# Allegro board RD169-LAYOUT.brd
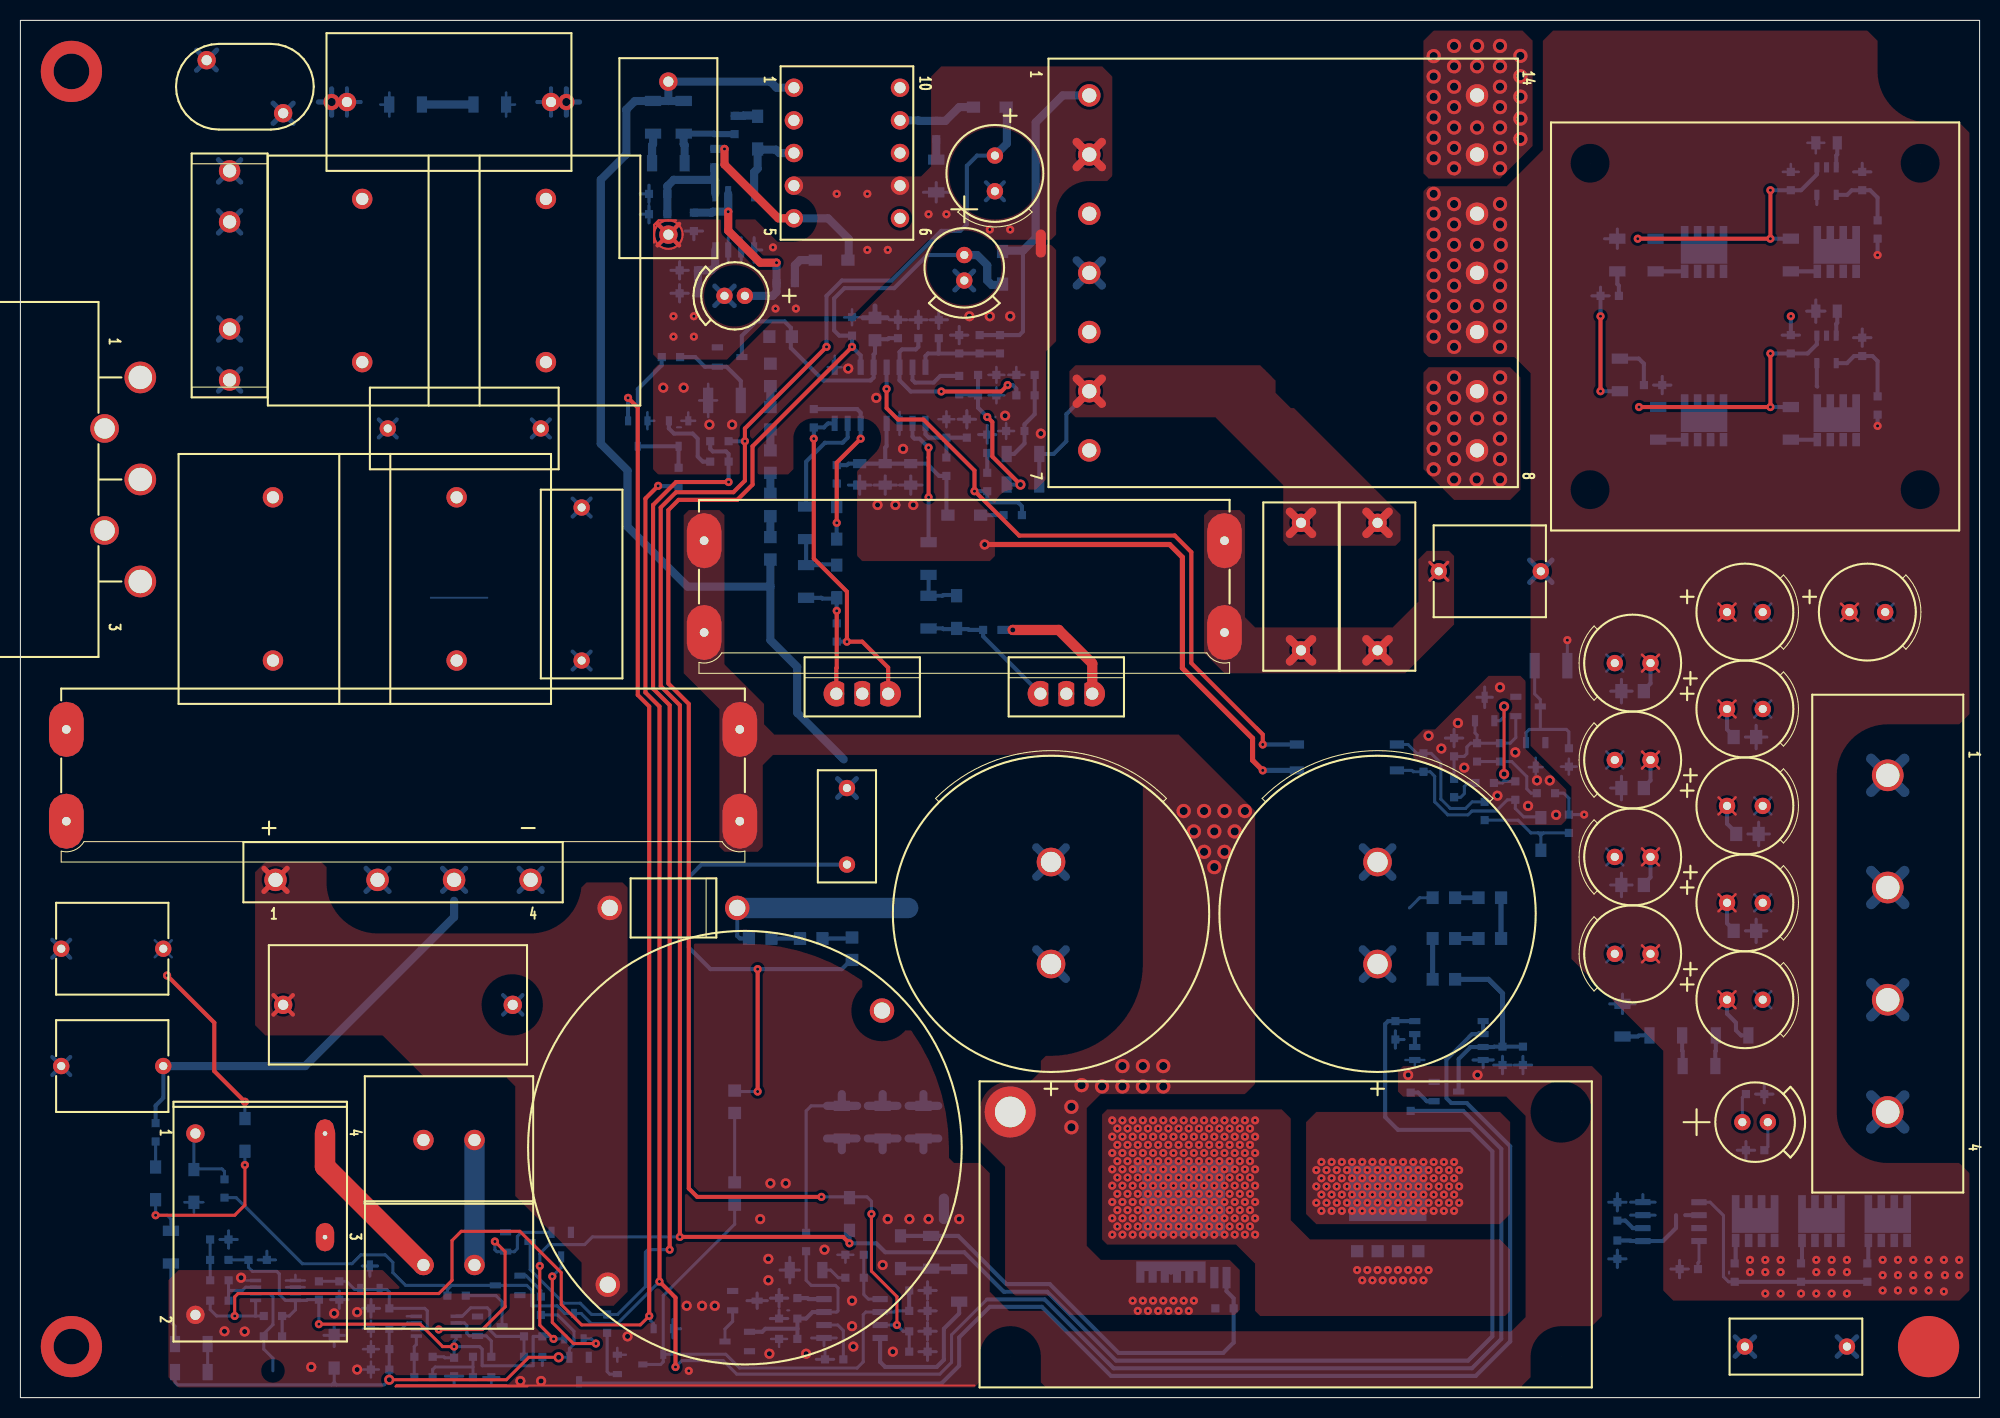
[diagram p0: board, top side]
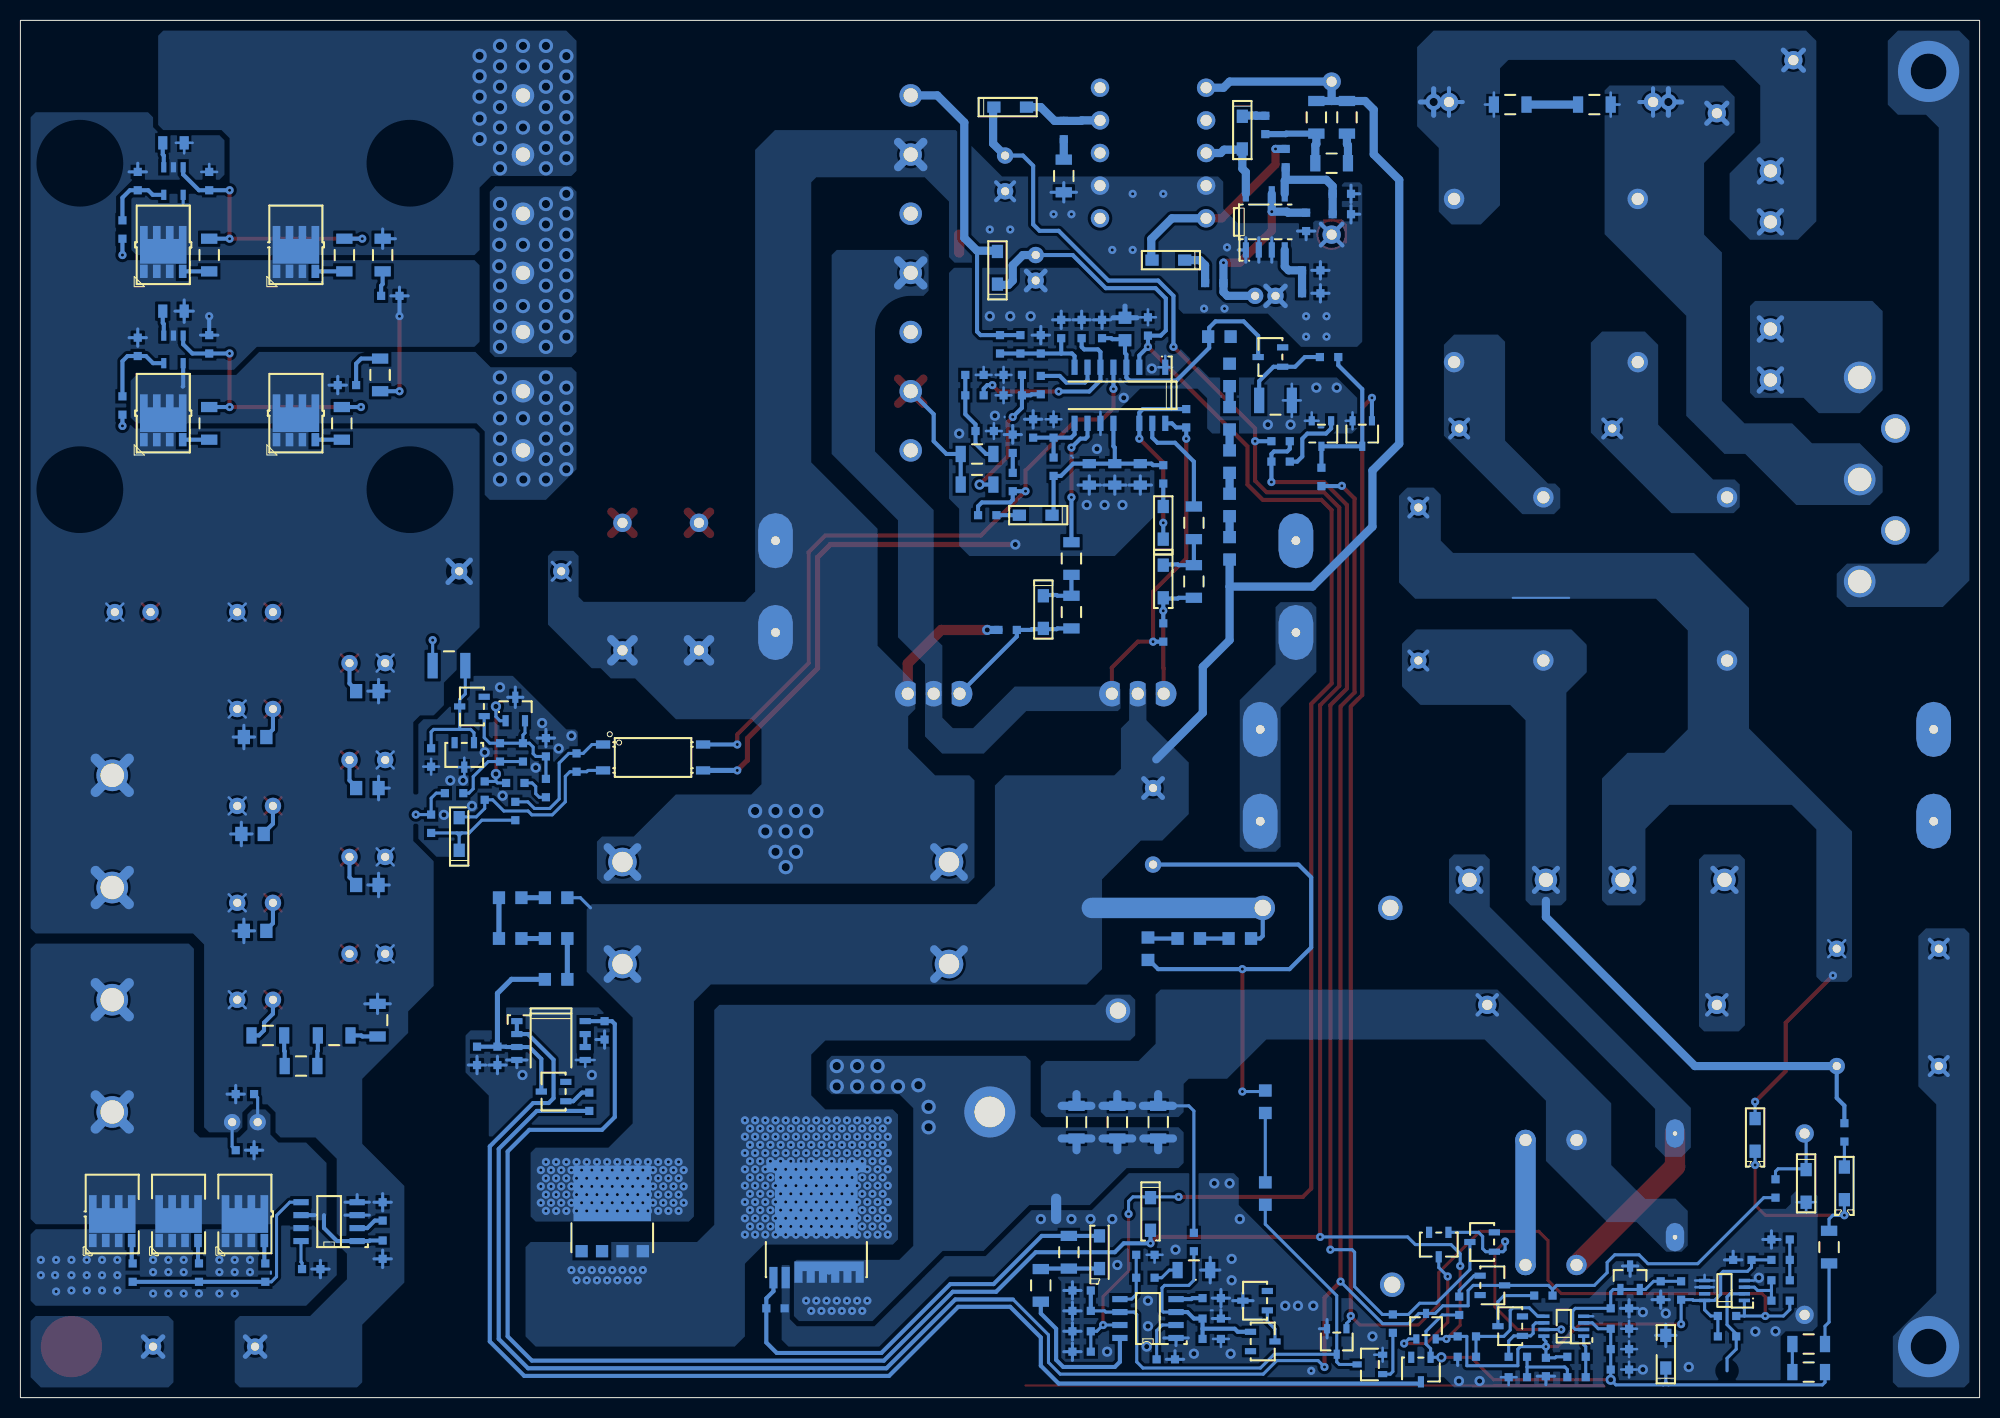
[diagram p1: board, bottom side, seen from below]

Outline 192 x 135 mm; copper layers: TOP, BOTTOM. Coordinates in mm from the lower left corner of the outline.
Outline path: rectangle 0,0 192,135

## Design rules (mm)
constraint set DEFAULT: 

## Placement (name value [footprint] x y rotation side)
C1  -  [RD10010SP01]  63.5 129 270 top
C2  -  [KC00080SP01]  35.25 4.75 180 bottom
C3  -  [KC00080SP01]  35.25 8.75 180 bottom
C4  -  [KC00140SP01]  65 125.5 270 bottom
C5  -  [RD10180SP01]  52 127 180 top
C6  -  [KC00080SP01]  75.25 7.75 180 bottom
C7  -  [KC00080SP01]  79.75 3.75 180 bottom
C8  -  [KC00080SP01]  45.25 2 0 bottom
C9  -  [RD10370SP01]  51 95 180 top
C10  -  [KC00080SP01]  66 115.25 270 bottom
C11  -  [DC03410SP01]  69 108 0 top
C12  -  [RD10370SP01]  55 72.25 90 top
C13  -  [RD10380SP01]  14 44 180 top
C14  -  [KC00140SP01]  77 12.5 180 bottom
C15  -  [RD10380SP01]  14 32.5 180 top
C16  -  [KC00080SP01]  81.75 14 180 bottom
C17  -  [KC00080SP01]  42.5 3 270 bottom
C18  -  [KC00080SP01]  89.75 124.25 270 bottom
C19  -  [KC00080SP01]  88 4.5 0 bottom
C20  -  [KC00080SP01]  88 6.5 0 bottom
C21  -  [KC00080SP01]  88 10.5 0 bottom
C22  -  [RD10300SP01]  95.5 118.25 90 top
C23  -  [RD10460SP02]  25.75 38.5 0 top
C24  -  [RD10450SP01]  81 59.75 270 top
C25  -  [KC00080SP01]  81.5 105 90 bottom
C26  -  [KC00080SP01]  86 104.75 90 bottom
C27  -  [KC00080SP01]  88 104.75 90 bottom
C28  -  [KC00080SP01]  90 104.75 90 bottom
C29  -  [DC903A0SP01]  69 97.75 180 bottom
C30  -  [KC00080SP01]  94.75 93.5 90 bottom
C31  -  [RD10210SP01]  133 52.5 270 top
C32  -  [RD10210SP01]  101 52.5 270 top
C33  -  [KC00080SP01]  23.25 13.5 0 bottom
C34  -  [KC00080SP01]  90.75 95 90 bottom
C35  -  [KC00080SP01]  147.25 33.5 270 bottom
C36  -  [KC00060SP02]  87.25 90.5 270 bottom
C37  -  [KC00060SP02]  84.75 90.5 270 bottom
C38  -  [KC00080SP01]  77.75 96 90 bottom
C39  -  [KC00060SP02]  82.25 90.5 270 bottom
C40  -  [KC00080SP01]  134.75 36 270 bottom
C41  -  [DC05080SP01]  92.5 109.5 90 top
C42  -  [RD10410SP01]  125.5 85.75 270 top
C43  -  [KC00080SP01]  31.25 10.5 270 bottom
C44  -  [KC00140SP01]  98.25 89.5 180 bottom
C45  -  [RD10410SP01]  133 85.75 270 top
C46  -  [KC00140SP01]  98.25 92.5 180 bottom
C47  -  [RD10380SP01]  139 81 0 top
C49  -  [KC00080SP01]  160 99.25 0 bottom
C50  -  [KC00080SP01]  155.75 108 0 bottom
C51  -  [KC00080SP01]  94.75 98.25 0 bottom
C52  -  [KC00080SP01]  94.75 100.25 0 bottom
C53  -  [KC00060SP02]  177 106.5 180 bottom
C54  -  [KC00080SP01]  180.5 103 90 bottom
C55  -  [KC00060SP02]  177 123 180 bottom
C56  -  [RD10300SP01]  182.75 77 180 top
C57  -  [RD10300SP01]  170.75 77 180 top
C58  -  [KC00080SP01]  180.5 119.25 90 bottom
C59  -  [RD10300SP01]  170.75 67.5 180 top
C60  -  [RD10300SP01]  170.75 58 180 top
C61  -  [RD10300SP01]  170.75 48.5 180 top
C62  -  [RD10300SP01]  170.75 39 180 top
C63  -  [RD10300SP01]  156.25 72 0 top
C64  -  [KC00080SP01]  143.5 60.25 0 bottom
C65  -  [KC00080SP01]  156.5 14.5 270 bottom
C66  -  [RD10300SP01]  156.25 62.5 0 top
C67  -  [RD10300SP01]  156.25 53 0 top
C68  -  [KC00080SP01]  142.75 63.25 90 bottom
C69  -  [RD10300SP01]  156.25 43.5 0 top
C70  -  [DC903A0SP01]  150 71.75 180 bottom
C71  -  [KC00060SP01]  169 64.75 0 bottom
C72  -  [KC00060SP01]  169.25 55.25 0 bottom
C73  -  [KC00080SP01]  163.5 12.6 0 bottom
C74  -  [KC00060SP01]  169 45.75 0 bottom
C75  -  [KC00060SP01]  158 69.25 180 bottom
C76  -  [KC00060SP01]  158 59.75 180 bottom
C77  -  [KC00060SP01]  158 50.25 180 bottom
C78  -  [DC05080SP01]  171.25 27 180 top
C79  -  [RD10430SP01]  179 5 180 top
C80  -  [KC00080SP01]  170 24.25 0 bottom
C81  -  [KC00080SP01]  170 29.75 0 bottom
D1  -  [MMK01670SP01]  13.25 21 270 bottom
D2  -  [MMK01670SP01]  22 25.75 270 bottom
D3  -  [MM10240SP01]  71 9.5 90 bottom
D4  -  [MM10240SP01]  47.75 11 270 bottom
D5  -  [MM10240SP01]  70.25 5.5 270 bottom
D6  -  [MMK01670SP01]  72.25 124 90 bottom
D7  -  [MM10240SP01]  46 7 90 bottom
D8  -  [MMK01670SP01]  79.5 111.5 180 bottom
D9  -  [MMK01670SP01]  81.25 18 90 bottom
D10  -  [D0001A0SP01]  25 50.75 0 top
D11  -  [MM10240SP01]  53 15 0 bottom
D12  -  [MM10240SP01]  48.75 15.25 90 bottom
D13  -  [MMK01670SP01]  17 20.75 90 bottom
D14  -  [MMK01670SP01]  95 126.5 0 bottom
D15  -  [RD10400SP01]  57.75 48 0 top
D16  -  [MMK01670SP01]  86.25 14.25 270 bottom
D17  -  [MM10240SP01]  139.75 30 90 bottom
D18  -  [MM11090SP01]  134 18.25 180 bottom
D19  -  [MM10240SP01]  69.5 102 90 bottom
D20  -  [MMK01670SP01]  80 80 90 bottom
D21  -  [MMK01670SP01]  91.75 77 90 bottom
D22  -  [MMK01670SP01]  80 85.75 270 bottom
D23  -  [MMK01670SP01]  96.25 110.75 270 bottom
D24  -  [MM10240SP01]  54.75 2.75 0 bottom
D25  -  [MM10240SP01]  147.75 67.75 90 bottom
D26  -  [MM10240SP01]  148.5 63 0 bottom
F1  -  [OD11240SP01]  20.5 99.75 90 top
HS1  -  [SE10220SP01]  70.5 65.5 180 top
HS2  -  [SE10240SP01]  97 28 0 top
HS3  -  [SE10160SP01]  153.82 89 0 top
HS4  -  [SE10230SP01]  118 84 180 top
L1  -  [OD11280SP01]  33.5 117.5 270 top
L2  -  [OD11280SP01]  24.75 88.25 270 top
L3  -  [OD11260SP01]  57.56 11.06 45 top
PC1  -  [MM11100SP01]  130 62.75 270 bottom
Q1  -  [DQ900A0SP01]  54.25 7 180 bottom
Q2  -  [DQ900A0SP01]  64.5 94.5 0 bottom
Q3  -  [DQ900A0SP01]  59.75 3.25 90 bottom
Q4  -  [DQ900A0SP01]  63 5.5 0 bottom
Q5  -  [DQ900A0SP01]  60.5 94.5 0 bottom
Q6  -  [MM11080SP01]  114 17 180 bottom
Q7  -  [SI10100SP01]  79.96 69 0 top
Q8  -  [SI10100SP01]  99.96 69 0 top
Q10  -  [SN00130SP01]  165 113 180 bottom
Q11  -  [SN00130SP01]  165 96.5 180 bottom
Q12  -  [SN00130SP01]  178 113 180 bottom
Q13  -  [SN00130SP01]  178 96.5 180 bottom
Q14  -  [SN00130SP01]  183 18 180 bottom
Q15  -  [SN00130SP01]  176.5 18 180 bottom
Q16  -  [SN00130SP01]  170 18 180 bottom
R1  -  [KC00080SP01]  35.25 6.75 180 bottom
R2  -  [KC00140SP01]  14.75 14.75 270 bottom
R3  -  [KC00140SP01]  16.75 5.25 0 bottom
R4  -  [KC00140SP01]  16.75 2.5 180 bottom
R5  -  [KC00080SP01]  35.25 2.75 180 bottom
R6  -  [KC00140SP01]  46 126.75 180 bottom
R7  -  [KC00140SP01]  37.75 126.75 180 bottom
R8  -  [KC00080SP01]  65.5 110.5 180 bottom
R9  -  [KC00080SP01]  51 9 90 bottom
R10  -  [KC00140SP01]  62 125.5 270 bottom
R11  -  [KC00140SP01]  63.5 121 0 bottom
R12  -  [KC00080SP01]  13.25 26 270 bottom
R13  -  [KC00080SP01]  65.5 108.25 180 bottom
R14  -  [KC00080SP01]  70 124.75 90 bottom
R15  -  [KC00080SP01]  75.25 5.75 180 bottom
R16  -  [KC00080SP01]  39.5 4 180 bottom
R17  -  [KC00080SP01]  39.5 2 0 bottom
R18  -  [KC00080SP01]  62.5 118 180 bottom
R19  -  [KC00080SP01]  77 15.25 270 bottom
R20  -  [KC00080SP01]  75.25 9.75 180 bottom
R21  -  [KC00080SP01]  62.5 116 180 bottom
R22  -  [KC00080SP01]  45.25 4 0 bottom
R23  -  [KC00080SP01]  68 121.5 270 bottom
R24  -  [KC00080SP01]  50.25 6 180 bottom
R25  -  [KC00080SP01]  50.25 4 0 bottom
R26  -  [KC00080SP01]  75 109.25 180 bottom
R27  -  [KC00080SP01]  42.75 10 180 bottom
R28  -  [KC00080SP01]  68.5 93.75 180 bottom
R29  -  [KC00080SP01]  81.75 11.75 180 bottom
R30  -  [KC00080SP01]  68.5 91.75 0 bottom
R31  -  [KC00080SP01]  57.5 7.25 90 bottom
R32  -  [KC00080SP01]  20 20.5 270 bottom
R33  -  [KC00140SP01]  89.75 119.75 270 bottom
R34  -  [OD11270SP01]  44.5 13 180 top
R35  -  [OD11270SP01]  39.5 25.25 0 top
R36  -  [KC00060SP03]  72.5 45 0 bottom
R37  -  [KC00060SP03]  77.5 45 0 bottom
R38  -  [KC00060SP03]  81.5 44 270 bottom
R39  -  [KC00060SP03]  70 29 270 bottom
R40  -  [KC00060SP03]  70 20 270 bottom
R41  -  [KC00080SP01]  88 8.5 0 bottom
R42  -  [KC00140SP01]  92 11 270 bottom
R43  -  [KC00140SP01]  88.5 27 270 bottom
R44  -  [KC00140SP01]  84.5 27 270 bottom
R45  -  [KC00140SP01]  80.5 27 270 bottom
R46  -  [KC00140SP01]  89.25 14.25 90 bottom
R47  -  [KC00080SP01]  136.25 29 90 bottom
R48  -  [KC00080SP01]  24.75 6 180 bottom
R49  -  [KC00080SP01]  118 8.75 0 bottom
R50  -  [KC00080SP01]  64.5 90.25 90 bottom
R51  -  [KC00080SP01]  63.75 102 180 bottom
R52  -  [KC00060SP03]  139.5 49 0 bottom
R53  -  [KC00060SP03]  144 49 0 bottom
R54  -  [KC00060SP03]  144 45 180 bottom
R55  -  [KC00060SP03]  139.5 45 180 bottom
R56  -  [KC00060SP03]  139.5 41 0 bottom
R57  -  [KC00080SP01]  145.25 33.5 270 bottom
R58  -  [KC00060SP03]  83.75 104.75 90 bottom
R59  -  [KC00080SP01]  92 103.25 90 bottom
R60  -  [KC00080SP01]  19.5 13.5 180 bottom
R61  -  [KC00080SP01]  19.5 15.5 0 bottom
R62  -  [KC00080SP01]  19.5 11.5 0 bottom
R63  -  [KC00060SP03]  73.5 83.25 90 bottom
R64  -  [KC00060SP03]  73.5 87.5 90 bottom
R65  -  [KC00060SP03]  73.5 91.75 90 bottom
R66  -  [KC00060SP03]  73.5 96 90 bottom
R67  -  [KC00060SP03]  73.5 100.25 90 bottom
R68  -  [KC00060SP03]  74.5 104 0 bottom
R69  -  [KC00080SP01]  19.5 9.5 180 bottom
R70  -  [KC00080SP01]  94.75 89.75 90 bottom
R71  -  [KC00080SP01]  96 103.25 270 bottom
R72  -  [KC00080SP01]  94 103.25 270 bottom
R73  -  [KC00080SP01]  98.5 98.25 0 bottom
R74  -  [KC00140SP01]  77 85.75 90 bottom
R75  -  [KC00080SP01]  24.75 8 180 bottom
R76  -  [KC00140SP01]  89 82.25 90 bottom
R77  -  [KC00140SP01]  77 80 270 bottom
R78  -  [KC00140SP01]  89 77 270 bottom
R79  -  [KC00080SP01]  90.75 91.25 90 bottom
R80  -  [KC00080SP01]  92.75 95 90 bottom
R81  -  [KC00080SP01]  80 75 270 bottom
R82  -  [KC00080SP01]  95.25 75.25 0 bottom
R83  -  [KC00080SP01]  80 90.5 90 bottom
R84  -  [KC00080SP01]  29.25 10.5 90 bottom
R85  -  [KC00080SP01]  98.5 100.25 180 bottom
R86  -  [KC00080SP01]  97.5 94.75 180 bottom
R88  -  [KC00140SP01]  156.5 112 270 bottom
R89  -  [KC00140SP01]  156.75 100.25 270 bottom
R91  -  [KC00080SP01]  173.5 103.25 270 bottom
R92  -  [KC00140SP01]  173.5 112 90 bottom
R93  -  [KC00140SP01]  160.25 112 90 bottom
R94  -  [KC00140SP01]  173.5 95.5 90 bottom
R95  -  [KC00140SP01]  160.5 95.5 90 bottom
R96  -  [KC00080SP01]  173.5 119.25 270 bottom
R97  -  [KC00080SP01]  97.25 86.5 180 bottom
R98  -  [KC00080SP01]  182 97.25 90 bottom
R99  -  [KC00080SP01]  182 114.5 270 bottom
R100  -  [KC00080SP01]  151.75 56.25 270 bottom
R101  -  [KC00080SP01]  143.5 57.5 90 bottom
R102  -  [KC00080SP01]  137.5 62.25 270 bottom
R103  -  [KC00080SP01]  146.5 59.5 90 bottom
R104  -  [KC00080SP01]  156.5 18.25 90 bottom
R105  -  [KC00080SP01]  140.5 59.75 90 bottom
R106  -  [KC00080SP01]  149.5 59.25 180 bottom
R107  -  [KC00080SP01]  145 63.25 90 bottom
R108  -  [KC00080SP01]  140.5 63.75 90 bottom
R109  -  [KC00140SP01]  157 37 270 bottom
R110  -  [KC00140SP01]  161.25 35.5 0 bottom
R111  -  [KC00140SP01]  164.5 32.5 0 bottom
R112  -  [KC00140SP01]  167.75 35.5 0 bottom
R113  -  [KC00080SP01]  181 12.25 270 bottom
R114  -  [KC00080SP01]  151.75 62.75 270 bottom
R115  -  [KC00080SP01]  174.5 12.25 270 bottom
R116  -  [KC00080SP01]  168 12.25 270 bottom
R117  -  [KC00080SP01]  92 99.25 270 bottom
RL1  -  [OD11250SP01]  15.55 27.95 270 top
T1  -  [OD11290SP01]  75.8 128.4 270 top
T2  -  [OD11300SP01]  104.75 127.65 270 top
TB1  -  [CT11580SP01]  11.75 100 270 top
TB2  -  [CU11710SP01]  183 61 270 top
TP1  -  [STAR2_SMT]  90.5 19.5 180 bottom
U1  -  [I810E40SP01]  40.75 7 90 bottom
U2  -  [SP10390SP01]  70 115.25 180 bottom
U3  -  [SP00870SP01]  81.5 7.75 90 bottom
U4  -  [I810E40SP01]  25 10.5 90 bottom
U5  -  [SP10380SP01]  84.25 98.25 0 bottom
U6  -  [SP10370SP01]  140 35 270 bottom
U7  -  [MM10490SP01]  34.25 11.75 180 bottom
U8  -  [MM00630SP01]  177 102.75 0 bottom
U9  -  [MM00630SP01]  177 119.25 0 bottom
U10  -  [MM10490SP01]  143.5 67.5 180 bottom
U11  -  [SP00870SP01]  161.75 17.25 90 bottom
VAR1  -  [RD10440SP01]  18.25 131.1 0 top
ZD1  -  [MMK01670SP01]  30.75 4.5 270 bottom
ZD2  -  [MMK01670SP01]  92.5 86.5 180 bottom
ZD3  -  [MMK01670SP01]  149 55.25 270 bottom

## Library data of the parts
C1 = DP0009391000
C2 = DP0009388000
C3 C18 C43 C49 C50 = DP0000017052
C4 = DP0009398000
C5 = DP0005068000
C6 C7 = DP0000017061
C8 C25 = DP0000017081
C9 C12 = DP0009392000
C10 C17 C20 C30 C33 C40 C64 C65 = DP0009323000
C11 = DP0009410000
C13 C15 C47 = DP0009393000
C14 = DP0002421002
C16 C34 = DP0009465000
C19 C38 C54 C58 = DP0000017034
C21 = DP0009325000
C22 = DP0009411000
C23 = DP0009492000
C24 = DP0009466000
C26 C28 = DP0009326000
C27 = DP0002439000
C29 = DP0006877000
C31 C32 = DP0009407000
C35 = DP0000017063
C36 C37 C39 C53 C55 = DP0009328000
C41 C78 = DP0009408000
C42 C45 = DP0009409000
C44 = DP0009493000
C46 = DP0009329000
C51 = DP0009467000
C52 = DP0009468000
C56 C57 C59-C63 C66 C67 C69 = DP0009330000
C68 = DP0000017053
C70 = DP0000727000
C71 C72 C74-C77 = DP0005401000
C73 = DP0000017058
C79 = DP0009421000
C80 C81 = DP0000017075
D1 D2 D13 = DP0010246000
D3-D5 D7 D11 D12 D17 D19 D24-D26 = DP0003799000
D6 D22 = DP0010245000
D8 D14 = DP9000889000
D9 D16 D20 D21 = DP0001001000
D10 = DP0009494000
D15 = DP0009405000
D18 = DP0010238000
D23 = DP0009334000
F1 = DP0009384000
HS1 = DP0010239000
HS2 = DP0010242000
HS3 = DP0009389000
HS4 = DP0010240000
L1 L2 = DP0009406000
L3 = DP0009402000
PC1 = DP0010243000
Q1 = DP0000428000
Q2-Q5 = DP0002713000
Q6 = DP0010237000
Q7 Q8 = DP0009387000
Q10-Q13 = DP0009335000
Q14-Q16 = DP0009336000
R1 = DP0000156122
R2-R4 = DP0009337000
R5 = DP0000156110
R6 R7 = DP0009338000
R8 = DP0000003085
R9 = DP0000156144
R10 R11 = DP0009340000
R12 R14 R98 R99 R113 R115 R116 = DP0000156000
R13 = DP0000156114
R15 = DP0000156048
R16 R91 R96 = DP0000156120
R17 = DP0000156064
R18 = DP0000156132
R19 R51 R104 = DP0000156056
R20 = DP0000003109
R21 = DP0000003105
R22 R102 = DP0000156080
R23 = DP0000003115
R24 R25 R28 R30 R31 R49 R72 R75 R81 R82 R97 = DP0000156096
R26 = DP0000156032
R27 = DP0000156104
R29 = DP0000156109
R32 = DP0000003045
R33 = DP0009345000
R34 R35 = DP0009495000
R36-R38 = DP0009413000
R39 = DP0009414000
R40 = DP0009415000
R41 = DP0009349000
R42 = DP0009350000
R43-R45 = DP0009416000
R46 = DP0010244000
R47 R84 R85 R105 = DP0000156088
R48 R59 R60 = DP0000003099
R50 = DP0000156136
R52-R56 = DP0000158126
R57 = DP0000003098
R58 = DP0009354000
R61 = DP0000003075
R62 = DP0000003087
R63-R67 = DP0009355000
R68 = DP0009356000
R69 = DP0000003119
R70 R80 = DP0000003136
R71 = DP0000003114
R73 R103 R117 = DP0000156177
R74 R76 = DP0009360000
R77 R78 = DP0009361000
R79 = DP0000003144
R83 = DP0000156009
R86 = DP0000156055
R88 R89 = DP0009364000
R92-R95 = DP0009365000
R100 = DP0000156084
R101 = DP0000156086
R106 = DP0000003055
R107 = DP0000147071
R108 = DP0009369000
R109-R112 = DP0009370000
R114 = DP0000156072
RL1 = DP0009376000
T1 = DP0009399000
T2 = DP0009400000
TB1 = DP0009374000
TB2 = DP0009375000
TP1 = ZS_STAR2
U1 U4 = DP0002205000
U2 = DP0009315000
U3 = DP0009316000
U5 = DP0009321000
U6 = DP0009317000
U7 U10 = DP0009318000
U8 U9 = DP0009319000
U11 = DP0009320000
VAR1 = DP0009404000
ZD1 = DP0009371000
ZD2 ZD3 = DP0009372000

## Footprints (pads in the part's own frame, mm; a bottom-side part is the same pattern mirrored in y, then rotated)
CT11580SP01
  round 2.8 hole 2.3: 1(0,0) 2(10,0) 3(20,0)
  round 2.5 hole 2: 1T(5,-3.5) 2T(15,-3.5)
CU11710SP01
  round 2.8 hole 2.3: 1(0,0) 2(11,0) 3(22,0) 4(33,0)
D0001A0SP01
  round 1.9 hole 1.4: 1(0,0) 2(10,0) 3(17.5,0) 4(25,0)
DC903A0SP01
  rect 1x2.5 smd: 1(-1.6,0) 2(1.6,0)
DC03410SP01
  round 1.3 hole 0.8: 1(0,0) 2(2,0)
DC05080SP01
  round 1.3 hole 0.8: 1(0,0) 2(2.5,0)
DQ900A0SP01
  rect 0.6x0.9 smd: B(-0.95,-1.25) C(0,1.25) E(0.95,-1.25)
I810E40SP01
  rect 0.35x1.1 smd: 1(-0.975,-1.95) 2(-0.325,-1.95) 3(0.325,-1.95) 4(0.975,-1.95) 5(0.975,1.95) 6(0.325,1.95) 7(-0.325,1.95) 8(-0.975,1.95)
KC00060SP01
  rect 1.2x1.4 smd: 1(-1.1,0) 2(1.1,0)
KC00060SP02
  rect 0.9x1.3 smd: 1(-1.05,0) 2(1.05,0)
KC00060SP03
  rect 1.2x1.25 smd: 1(-1.1,0) 2(1.1,0)
KC00080SP01
  rect 0.8x0.8 smd: 1(-0.9,0) 2(0.9,0)
KC00140SP01
  rect 1x1.6 smd: 1(-1.6,0) 2(1.6,0)
MM00630SP01
  rect 0.5x1 smd: 1(-0.95,-1.35) 2(0,-1.35) 3(0.95,-1.35) 4(0.95,1.35) 5(-0.95,1.35)
MM10240SP01
  rect 0.6x1.1 smd: A(0,1.2) C(-0.95,-1.2) NC(0.95,-1.2)
MM10490SP01
  rect 0.6x1.1 smd: 1(-0.95,-1.15) 2(0.95,-1.15) 3(0,1.15)
MM11080SP01
  rect 0.8x2.1 smd: 1(-4.2,-5.24) 2(-3,-5.24)
  custom 0.525x0.525 smd: 3(1.25,-4.7)
  custom 1.863x1.863 smd: 9(0,2.55)
MM11090SP01
  rect 1.2x1.2 smd: 1(-3,-3.9) 2(-1,-3.9) 3(1,-3.9) 4(3,-3.9)
  rect 7.6x5.45 smd: 5(0,1.775)
MM11100SP01
  rect 0.8x1.4 smd: A(-1.27,-4.9) C(-1.27,4.9) CA(1.27,-4.9) E(1.27,4.9)
MMK01670SP01
  rect 1.3x1.1 smd: A(-1.6,0) C(1.6,0)
OD11240SP01
  round 2.1 hole 1.3: 1(0,0) 2(5,0) 3(15.5,0) 4(20.5,0)
OD11250SP01
  round 1.8 hole 1: 1(2.06,1.6) 2(19.84,1.6)
  custom 0.45x0.45 hole 2x0.8: 3(12.22,14.3) 4(2.06,14.3)
OD11260SP01
  round 2.4 hole 1.6: 1(0,0) 2(38,0)
OD11270SP01
  round 2 hole 1.2: 1(0,0) 2(5,0)
OD11280SP01
  round 2 hole 1.2: 1(0,0) 2(16,0) 3(16,18) 4(0,18)
OD11290SP01
  round 1.6 hole 1.1: 1(0,0) 2(3.2,0) 3(6.4,0) 4(9.6,0) 5(12.8,0) 6(12.8,10.4) 7(9.6,10.4) 8(6.4,10.4) 9(3.2,10.4) 10(0,10.4)
OD11300SP01
  round 1.9 hole 1.4: 1(0,0) 2(5.8,0) 3(11.6,0) 4(17.4,0) 5(23.2,0) 6(29,0) 7(34.8,0) 8(34.8,38) 9(29,38) 10(23.2,38) 11(17.4,38) 12(11.6,38) 13(5.8,38) 14(0,38)
RD10010SP01
  round 1.5 hole 1: 1(0,0) 2(15,0)
RD10180SP01
  round 1.5 hole 1: 1(0,0) 2(20,0)
RD10210SP01
  round 2.5 hole 2: 1(0,0) 2(10,0)
RD10300SP01
  round 1.3 hole 0.8: 1(0,0) 2(3.5,0)
RD10370SP01
  round 1.6 hole 0.8: 1(0,0) 2(15,0)
RD10380SP01
  round 1.3 hole 0.8: 1(0,0) 2(10,0)
RD10400SP01
  round 2.4 hole 1.6: A(0,0) C(12.5,0)
RD10410SP01
  round 1.5 hole 1: 1(0,0) 2(12.5,0)
RD10430SP01
  round 1.3 hole 0.8: 1(0,0) 2(10,0)
RD10440SP01
  round 1.8 hole 1: 1(0,0) 2(7.5,-5.2)
RD10450SP01
  round 1.3 hole 0.8: 1(0,0) 2(7.5,0)
RD10460SP02
  round 1.5 hole 1: 1(0,0) 2(22.5,0)
SE10160SP01
  round 0.01 hole 2.8 unplated: (0,32) (0,0) (32.35,32) (32.35,0)
SE10220SP01
  custom 0.85x0.85 hole 1.4x3.4: 1T(0,0) 2T(0,9) 3T(66,0) 4T(66,9)
SE10230SP01
  custom 0.85x0.85 hole 1.4x3.4: 1T(0,0) 2T(0,9) 3T(51,0) 4T(51,9)
SE10240SP01
  round 0.01 hole 3 unplated: (0,-24) (54,0) (54,-24)
  round 5 hole 3: 1T(0,0)
SI10100SP01
  round 1.54 hole 1.2: D(2.54,0) G(0,0) S(5.08,0)
SN00130SP01
  rect 0.75x1.3 smd: 1(-1.905,-2.6) 2(-0.635,-2.6) 3(0.635,-2.6) 4(1.905,-2.6)
  custom 0.925x0.925 smd: 5(0,0)
SP00870SP01
  rect 0.6x1.5 smd: 1(-1.905,-2.75) 2(-0.635,-2.75) 3(0.635,-2.75) 4(1.905,-2.75) 5(1.905,2.75) 6(0.635,2.75) 7(-0.635,2.75) 8(-1.905,2.75)
SP10370SP01
  rect 0.6x1.1 smd: 1(-1.905,-3.35) 2(-0.635,-3.35) 3(0.635,-3.35) 4(1.905,-3.35) 5(1.905,3.35) 6(0.635,3.35) 7(-0.635,3.35) 8(-1.905,3.35)
SP10380SP01
  rect 0.6x1.5 smd: 1(-4.445,-2.75) 3(-1.905,-2.75) 4(-0.635,-2.75) 5(0.635,-2.75) 6(1.905,-2.75) 7(3.175,-2.75) 8(4.445,-2.75) 9(4.445,2.75) 10(3.175,2.75) 11(1.905,2.75) 12(0.635,2.75) 14(-1.905,2.75) 15(-3.175,2.75) 16(-4.445,2.75)
SP10390SP01
  rect 0.6x1.5 smd: 1(-1.905,-2.75) 2(-0.635,-2.75) 3(0.635,-2.75) 4(1.905,-2.75) 5(1.905,2.75) 6(0.635,2.75) 8(-1.905,2.75)
STAR2_SMT
  round 0.02 smd: 1(0,0) 2(0,0)

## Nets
12VREC: C56.2 C57.2 C59.2 C60.2 C61.2 C62.2 C63.2 C66.2 C67.2 C69.2 C70.1 C71.1 C72.1 C73.1 C74.1 C75.1 C76.1 C77.1 Q14.1 Q14.2 Q14.3 Q15.1 Q15.2 Q15.3 Q16.1 Q16.2 Q16.3 R98.1 R99.2 R100.1 R106.1 R112.2 T2.10 T2.11 T2.12 U11.7
GND_PRI_P: C1.2 C10.2 C11.1 C22.1 C25.2 C26.2 C27.2 C28.2 C29.2 C30.2 C31.1 C32.1 C34.2 C36.2 C37.2 C39.2 C41.1 C42.2 C45.2 C47.1 C51.2 C52.2 HS1.1T HS1.2T HS2.1T HS4.1T HS4.2T HS4.3T HS4.4T PC1.E Q2.E Q5.E Q6.3 Q8.S R8.2 R13.2 R18.2 R21.2 R33.2 R43.2 R44.2 R45.2 R58.2 R59.2 R80.2 R82.2 R85.2 R86.2 T1.4 T1.7 T2.2 TP1.2 U2.1 U2.2 U2.3 U5.1 U5.11
GND_PRI_S: C2.2 C3.2 C6.2 C7.2 C8.2 C14.2 C16.2 C17.2 C19.2 C20.2 C21.2 C33.2 C35.2 C40.2 C43.2 D3.A D13.A Q3.E Q4.E Q6.2 R1.2 R5.2 R15.2 R20.2 R25.2 R41.2 R49.1 R57.2 R61.2 RL1.2 TP1.1 U1.4 U3.1 U4.4 U4.5 U4.6 U6.4 U6.5 U7.3 ZD1.A
GND_SEC: C47.2 C50.1 C53.2 C54.2 C55.2 C56.1 C57.1 C58.2 C59.1 C60.1 C61.1 C62.1 C63.1 C65.2 C66.1 C67.1 C69.1 C71.2 C72.2 C74.2 C75.2 C76.2 C77.2 C78.1 C79.2 C80.2 C81.2 D26.A Q10.1 Q10.2 Q10.3 Q11.1 Q11.2 Q11.3 Q12.1 Q12.2 Q12.3 Q13.1 Q13.2 Q13.3 R89.2 R91.1 R96.1 R104.2 R108.2 R109.1 R114.2 TB2.1 TB2.2 U8.2 U9.2 U10.3 U11.3 U11.4
VCC-IC: C19.1 C20.1 C25.1 C41.2 D9.C D23.C U3.7 U5.3
VCC_P1: C17.1 C22.2 C33.1 C40.1 D9.A D14.C Q1.E R16.1 R24.1 R28.1 R48.1 R60.1 R75.1 R84.1 U1.8 U4.8 U6.8
+HV: C1.1 C4.1 C24.1 C31.2 C32.2 D15.C D18.5 Q7.D R10.1 R36.1 R52.1 R63.1 T1.1
ACINREC: D1.C D2.C R2.1
ACINVDET1: D11.A Q1.B
ACINVDET2: D12.A R28.2 R30.2 R31.2
BLK: C26.1 D19.A R58.1 R68.2 U5.4
BW: D23.A R71.1 R72.1 T2.1
FG1: C79.1
FG2: TB1.3
FG3: C13.2 C15.2
HI_GATE: R74.2 U5.15
HS: C38.1 Q7.S Q8.D R81.2 T2.4 U5.16
HV+SENS: C35.1 D17.A R56.2 R57.1 U6.3
HVDET: C2.1 D24.C R1.1 R4.2 R5.1 R9.1 U1.3 ZD1.C
ISENSE: C23.2 R19.1 R35.1 R43.1 R44.1 R45.1 RL1.3
ISNS_VCR: C42.1 C44.1 C45.1 C46.1 T2.6
LO_GATE: R76.2 U5.10
OR_GATE: R113.2 R115.2 R116.2 U11.5
OTP: Q4.B Q5.B R69.2 R75.2 U4.1
PC1_A: PC1.A R101.2 R102.1
PC1_CA: PC1.CA R102.2 R103.1 ZD3.A
PFC_GATE: D16.C R42.1 R46.1
RELAY_12V_ON_OFF: D4.A Q1.C R27.2 R32.2 R47.1 R50.1
RVCC: C36.1 C37.1 C39.1 R79.1 R83.2 U5.12 ZD2.C
SIG219: C9.1 L1.3 L2.4
SIG222: C12.1 C15.1 D10.3 L2.3 R12.1
SIG226: C12.2 C13.1 D2.A D10.2 L2.2
SIG231: D18.3 D18.4 L3.2 Q6.9
SIG232: F1.1 F1.2 TB1.1
SIG233: R34.1 R35.2
SIG236: R6.2 R7.1
SIG237: C5.1 F1.3 F1.4 L1.4 R6.1 VAR1.1
SIG239: C9.2 L1.2 L2.1
SIG242: C5.2 L1.1 R7.2 TB1.2 VAR1.2
SIG245: R2.2 R3.1
SIG246: C8.1 R17.2 R22.1
SIG247: R3.2 R4.1
SIG248: D11.C D12.C U1.7
SIG250: D7.A R27.1
SIG255: D17.C R47.2
SIG256: D4.C R9.2
SIG267: D24.A U6.1 U6.2
SIG270: U6.6 U6.7
SIG278: C10.1 C11.2 R26.2 U2.6
SIG280: D8.C R26.1
SIG281: C4.2 R11.2 R14.1
SIG283: R10.2 R11.1
SIG284: D6.A T1.3 U2.8
SIG285: C18.2 R33.1
SIG286: D8.A R23.1 T1.5
SIG287: C18.1 D14.A T1.9
SIG288: R18.1 R21.1 R23.2 U2.5
SIG290: R8.1 R13.1 U2.4
SIG316: R66.2 R67.1
SIG318: R65.2 R66.1
SIG319: R37.2 R38.1
SIG320: R36.2 R37.1
SIG321: R64.2 R65.1
SIG322: R39.2 R40.1
SIG323: R63.2 R64.1
SIG327: R67.2 R68.1
SIG328: C24.2 R38.2 R39.1
SIG332: R54.2 R55.1
SIG333: R53.2 R54.1
SIG334: R52.2 R53.1
SIG335: R55.2 R56.1
SIG341: Q2.C Q5.C R50.2 R51.2
SIG345: R42.2 U3.8
SIG348: C29.1 D19.C R51.1
SIG351: R20.1 U3.4
SIG353: Q2.B R30.1
SIG354: C7.1 U3.2
SIG356: C16.1 R29.1 U3.5
SIG357: Q3.B R31.1
SIG358: C14.1 R29.2
SIG359: C6.1 D5.C R15.1 R19.2 U3.3
SIG381: D21.A Q8.G R78.2 R82.1
SIG383: D20.A Q7.G R77.2 R81.1
SIG387: D20.C R74.1 R77.1
SIG392: D21.C R76.1 R78.1
SIG395: C46.2 R73.2 R85.1 R86.1
SIG396: C44.2 C51.1 C52.1 R117.2
SIG401: C28.1 R59.1 R71.2 R72.2 U5.8
SIG404: C30.1 R70.2
SIG406: R117.1 U5.7
SIG407: C38.2 D22.C U5.14
SIG409: R97.2 ZD2.A
SIG415: C50.2 R88.2
SIG416: C55.1 U9.3
SIG417: C49.1 R89.1
SIG418: C53.1 U8.3
SIG420: C54.1 R98.2 U8.4
SIG422: Q13.4 R94.1
SIG423: Q11.4 R95.1
SIG425: R92.2 R93.2 R96.2 U9.1
SIG426: Q12.4 R92.1
SIG430: Q10.4 R93.1
SIG431: R91.2 R94.2 R95.2 U8.1
SIG435: C58.1 R99.1 U9.4
SIG438: R109.2 R110.1
SIG439: R110.2 R111.1
SIG440: Q16.4 R116.1
SIG441: C65.1 C78.2 C80.1 C81.1 Q14.5 Q15.5 Q16.5 TB2.3 TB2.4 U11.1 U11.6
SIG442: C73.2 U11.8
SIG444: Q15.4 R115.1
SIG445: Q14.4 R113.1
SIG446: R104.1 U11.2
SIG447: R111.2 R112.1
SIG452: R100.2 R101.1 ZD3.C
SIG454: C64.1 R105.1
SIG455: C68.1 R106.2 R107.1
SIG458: C70.2 D25.A D26.C R114.1
SIG460: C64.2 R103.2 U10.1
SIG461: R24.2 R25.1 U1.5
SIG462: R16.2 R17.1 U1.1
SIG464: C34.1 R79.2 R80.1 U5.9
SIG466: C27.1 R73.1 U5.6
SIG469: R60.2 R61.1 R62.1
SIG470: R48.2 U4.2
SIG471: R62.2 R69.1 U4.3
SIG489: D7.C R22.2 U1.6
SIG490: D3.C D5.A
SIG491: C68.2 D25.C R105.2 R107.2 R108.1 U10.2
SIG508: PC1.C R70.1 R97.1 U5.5
SIG519: D13.C R32.1 RL1.1
SIG520: D1.A R12.2
SIG521: D6.C R14.2
SIG522: D22.A R83.1
SIG529: D16.A Q6.1 R46.2 R49.2
SIG535: D10.4 R34.2 RL1.4
SIG536: C23.1 D10.1 D15.A L3.1
U8_5: C49.2 Q11.5 Q13.5 T2.8 T2.9 U8.5
U9_5: Q10.5 Q12.5 R88.1 T2.13 T2.14 U9.5
VREF: C3.1 C43.1 R84.2 U1.2 U7.1 U7.2
VSENSE: C21.1 Q3.C Q4.C R40.2 R41.1 U3.6

Pads without a net: D3 NC; D4 NC; D5 NC; D7 NC; D11 NC; D12 NC; D17 NC; D18 1 2; D19 NC; D24 NC; D25 NC; D26 NC; HS1 3T 4T; T1 2 6 8 10; T2 3 5 7; TB1 1T 2T; U4 7

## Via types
v1: diameter 0.8, hole 0.3, TOP to BOTTOM, 458 vias
v2: diameter 1, hole 0.5, TOP to BOTTOM, 65 vias
v3: diameter 1.4, hole 0.8, TOP to BOTTOM, 93 vias
v4: diameter 1.6, hole 0.8, TOP to BOTTOM, 2 vias
v5: diameter 6, hole 3.5, TOP to BOTTOM, 2 vias
v6: diameter 0.01, hole 3.5, TOP to BOTTOM, 1 via

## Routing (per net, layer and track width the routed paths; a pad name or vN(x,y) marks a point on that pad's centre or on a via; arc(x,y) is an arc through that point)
12VREC: length 83.7
  TOP w0.25: C60.2 166.42,58.83 ; C60.2 168.08,58.83 ; C60.2 166.42,57.17 ; C60.2 168.08,57.17 ; C62.2 168.08,39.83 ; C62.2 168.08,38.17 ; C62.2 166.42,38.17 ; C62.2 166.42,39.83 ; C69.2 158.92,44.33 ; C69.2 160.58,42.67 ; C69.2 160.58,44.33 ; C69.2 158.92,42.67 ; C56.2 180.08,76.17 ; C56.2 180.08,77.83 ; C56.2 178.42,76.17 ; C56.2 178.42,77.83 ; C67.2 160.58,52.17 ; C67.2 160.58,53.83 ; C67.2 158.92,52.17 ; C67.2 158.92,53.83 ; C59.2 168.08,66.67 ; C59.2 166.42,68.33 ; C59.2 168.08,68.33 ; C59.2 166.42,66.67 ; C57.2 166.42,76.17 ; C57.2 168.08,76.17 ; C57.2 168.08,77.83 ; C57.2 166.42,77.83 ; C63.2 160.58,72.83 ; C63.2 158.92,71.17 ; C63.2 160.58,71.17 ; C63.2 158.92,72.83 ; C61.2 168.08,49.33 ; C61.2 166.42,49.33 ; C61.2 166.42,47.67 ; C61.2 168.08,47.67 ; C66.2 160.58,63.33 ; C66.2 158.92,61.67 ; C66.2 158.92,63.33 ; C66.2 160.58,61.67
  BOTTOM w0.2: 167.45,12.15 167.45,12.35
  BOTTOM w0.3: C73.1 163.45,12.6 ; C73.1 161.75,12.6 ; C73.1 162.6,11.75 ; C73.1 162.6,13.45 ; R106.1 151.25,59.25 151.75,58.75 R100.1 v1(153.25,57.15) ; C70.1 v1(151.6,74.25)
  BOTTOM w0.4: C59.2 167.25,65.5 168,64.75 ; C63.2 159.75,70 159,69.25 ; C61.2 167.25,46.5 168,45.75 ; C66.2 159.75,60.5 159,59.75 ; R98.1 v1(182,95.25) ; C67.2 159.75,51 159,50.25 ; C60.2 167.25,56.25 168.25,55.25 ; R112.2 168.62,35.5 168.12,36 168.12,36.75 167.25,37.62 C62.2 ; v1(182,112) R99.2
  vias: v1(169.5,13.5) v1(169.5,12.3) v1(171,13.5) v1(171,12.3) v1(171,10.2) v1(172.5,13.5) v1(172.5,12.3) v1(172.5,10.2) v1(174.5,10.2) v1(176,13.5) v1(176,12.3) v1(176,10.2) v1(177.5,13.5) v1(177.5,12.3) v1(177.5,10.2) v1(179,13.5) v1(179,12.3) v1(179,10.2) v1(182.5,13.5) v1(182.5,12) v1(182.5,10.5) v1(184,13.5) v1(184,12) v1(184,10.5) v1(185.5,13.5) v1(185.5,12) v1(185.5,10.5) v1(187,13.5) v1(187,12) v1(187,10.5) v1(188.5,13.5) v1(188.5,10.4) v1(188.6,12) v1(190,13.5) v1(190,12) v3(138.5,118) v3(138.5,116.05) v3(138.5,114) v3(138.5,112) v3(138.5,110) v3(138.5,108) v3(138.5,106) v3(138.5,104) v3(140.5,117) v3(140.5,115) v3(140.5,113) v3(140.5,111) v3(140.5,109) v3(140.5,107) v3(140.5,105) v3(140.5,103) v3(142.75,113) v3(142.75,107) v3(145,117) v3(145,115) v3(145,109) v3(145,107) v3(145,105) v3(145,103) v3(145.07,113) v3(145.07,110.9)
GND_PRI_P: length 275.6
  TOP w0.2: 63.5,115.4 62.54,115.4 62.1,114.96 62.1,113.22 ; 63.5,115.4 64.26,115.4 ; 63.5,115.4 arc(62.51,113.01) 64.9,114 arc(64.49,114.99) 63.5,115.4
  TOP w0.3: C47.1 139.88,81.88 ; C47.1 138.12,80.12 ; C47.1 138.12,81.88 ; C47.1 139.88,80.12
  TOP w0.4: C1.2 62.44,112.94 ; C1.2 64.56,115.06 ; C1.2 62.44,115.06 ; C1.2 64.56,112.94
  TOP w0.5: v1(121.75,61.48) 120.75,62.48 120.75,64.62 113.88,71.5 113.88,82.38 112.62,83.62 v2(94.5,83.62)
  TOP w0.8: C42.2 126.6,74.35 ; C42.2 126.6,72.15 ; C42.2 124.4,74.35 ; C42.2 124.4,72.15 ; C45.2 131.9,74.35 ; C45.2 134.1,72.15 ; C45.2 134.1,74.35 ; C45.2 131.9,72.15 ; T2.2 103.51,120.61 ; T2.2 103.51,123.09 ; T2.2 105.99,120.61 ; T2.2 105.99,123.09
  TOP w1: Q8.S 105.04,71.96 101.75,75.25 v2(97.25,75.25) ; 100,112.25 100,114
  BOTTOM w0.2: 94.72,95.33 94.78,95.33 ; 88.97,92.33 89.03,92.33 ; 88.88,92.15 88.85,92.15 ; 95.55,96.16 95.55,96.09 ; 64.75,95.11 64.34,95.11
  BOTTOM w0.25: Q2.E 66.12,95.75 ; Q2.E 64.78,95.75 ; Q2.E 65.45,96.58 ; C52.2 96.42,100.25 ; C52.2 95.65,101.03 ; C52.2 95.65,99.47 ; C52.2 94.88,100.25 ; C34.2 91.53,95.9 ; C34.2 89.97,95.9 ; C34.2 90.75,96.67 ; C34.2 90.75,95.12 ; Q5.E 61.45,94.92 ; Q5.E 62.12,95.75 ; Q5.E 61.45,96.58 ; 86.16,94.38 U5.11 86.16,96.62 ; C51.2 94.88,98.25 ; C51.2 95.65,99.03 ; C51.2 95.65,97.47 ; C51.2 96.42,98.25 ; U5.1 79.13,101 ; U5.1 79.81,102.12 ; U5.1 80.48,101 ; R85.2 98.38,100.25 ; R85.2 97.6,101.03 ; R85.2 96.83,100.25 ; C29.2 67.4,96.12 ; C29.2 67.4,99.38 ; C29.2 68.28,97.75 ; C29.2 66.53,97.75 ; R86.2 96.6,93.97 ; R86.2 96.6,95.53 ; R86.2 97.38,94.75 ; R86.2 95.83,94.75 ; C25.2 81.5,105.12 ; C25.2 82.28,105.9 ; C25.2 81.5,106.67 ; C25.2 80.72,105.9
  BOTTOM w0.3: R8.2 65.45,110.5 ; R8.2 64.6,111.35 ; R8.2 63.75,110.5 ; R8.2 64.6,109.65 ; R80.2 91.9,95.9 ; R80.2 92.75,95.05 ; R80.2 92.75,96.75 ; R80.2 93.6,95.9 ; R59.2 92.85,104.15 ; R59.2 92,105 ; R59.2 92,103.3 ; R59.2 91.15,104.15 ; C36.2 87.25,88.55 ; C36.2 88.35,89.45 ; C36.2 87.25,90.35 ; C36.2 86.15,89.45 ; C37.2 85.85,89.45 ; C37.2 84.75,88.55 ; C37.2 84.75,90.35 ; C37.2 83.65,89.45 ; U2.1 72.66,112.5 ; U2.1 71.91,111.3 ; U2.1 71.91,113.7 ; 70.64,113.7 U2.2 70.64,111.3 ; C47.1 138.12,80.12 ; C47.1 138.12,81.88 ; C47.1 139.88,81.88 ; C47.1 139.88,80.12 ; C10.2 65.15,114.35 ; C10.2 66,113.5 ; C10.2 66.85,114.35 ; C26.2 86,106.5 ; C26.2 86.85,105.65 ; C26.2 86,104.8 ; C26.2 85.15,105.65 ; C39.2 81.15,89.45 ; C39.2 82.25,88.55 ; C39.2 83.35,89.45 ; C39.2 82.25,90.35 ; R18.2 61.6,117.15 ; R18.2 60.75,118 ; R18.2 61.6,118.85 ; C27.2 88,104.8 ; C27.2 88,106.5 ; C27.2 87.15,105.65 ; C27.2 88.85,105.65 ; 69.36,111.3 U2.3 69.36,113.7 ; R13.2 64.6,109.1 ; R13.2 64.6,107.4 ; R13.2 65.45,108.25 ; R13.2 63.75,108.25 ; C28.2 90,106.5 ; C28.2 90,104.8 ; C28.2 90.85,105.65 ; C28.2 89.15,105.65 ; R21.2 61.6,116.85 ; R21.2 61.6,115.15 ; R21.2 60.75,116 ; C30.2 95.6,94.4 ; C30.2 94.75,95.25 ; C30.2 93.9,94.4 ; C30.2 94.75,93.55 ; R33.2 91,118.15 ; R33.2 89.75,117.2 ; R33.2 89.75,119.1 ; R33.2 88.5,118.15
  BOTTOM w0.4: C22.1 96.38,119.13 ; C22.1 96.38,117.37 ; C22.1 94.62,119.13 ; C22.1 94.62,117.37 ; C1.2 64.56,112.94 ; C1.2 64.56,115.06 ; C1.2 62.44,115.06 ; C1.2 62.44,112.94
  BOTTOM w0.5: PC1.E v1(121.75,61.48) ; R58.2 83.75,107 ; R58.2 84.92,105.85 ; R58.2 82.58,105.85 ; C11.1 68.05,108.95 ; C11.1 68.05,107.05 ; C11.1 69.95,107.05 ; C11.1 69.95,108.95 ; C41.1 91.58,110.42 ; C41.1 91.58,108.58 ; C41.1 93.42,110.42 ; C41.1 93.42,108.58
  BOTTOM w0.8: T2.2 103.51,120.61 ; T2.2 105.99,123.09 ; T2.2 103.51,123.09 ; T2.2 105.99,120.61 ; C45.2 134.1,74.35 ; C45.2 131.9,72.15 ; C45.2 131.9,74.35 ; C45.2 134.1,72.15 ; C32.1 102.45,51.05 ; C32.1 102.45,53.95 ; C32.1 99.55,51.05 ; C32.1 99.55,53.95 ; R45.2 81.95,25.4 ; R45.2 79.05,25.4 ; R45.2 80.5,24.25 ; R44.2 85.95,25.4 ; R44.2 84.5,24.25 ; R44.2 83.05,25.4 ; R43.2 87.05,25.4 ; R43.2 89.95,25.4 ; R43.2 88.5,24.25 ; C42.2 126.6,72.15 ; C42.2 124.4,72.15 ; C42.2 124.4,74.35 ; C42.2 126.6,74.35 ; v2(97.25,75.25) R82.2 ; C31.1 131.55,53.95 ; C31.1 131.55,51.05 ; C31.1 134.45,53.95 ; C31.1 134.45,51.05
  vias: v1(64,106) v1(64,104) v1(66,106) v1(66,104) v1(73.75,112.75) v1(74,106.75) v1(76,106.75) v1(80,118) v1(83,118) v1(83,112.5) v1(85,112.5) v1(89,116) v1(90.75,116) v1(95,114.5) v1(97,114.5) v1(109,9.5) v1(109.5,8.5) v1(110,9.5) v1(110.5,8.5) v1(111,9.5) v1(111.5,8.5) v1(112,9.5) v1(112.5,8.5) v1(113,9.5) v1(113.5,8.5) v1(114,9.5) v1(114.5,8.5) v1(115,9.5) v2(63,99) v2(65,99) v2(67.53,95.38) v2(69.75,95.38) v2(81.12,100.88) v2(83.88,98) v2(84,87.5) v2(85.75,87.5) v2(86.5,93) v2(87.5,87.5) v2(93,106) v2(95,106) v2(96.5,96.25) v2(97,106) v2(100,94.5) v3(103,28.5) v3(103,26.5) v3(104,30.62) v3(106,30.5) v3(108,32.5) v3(108,30.5) v3(110,32.5) v3(110,30.5) v3(112,32.5) v3(112,30.5) v3(114,57.5) v3(115,55.5) v3(116,57.5) v3(116,53.5) v3(117,55.5) v3(117,52) v3(118,57.5) v3(118,53.5) v3(119,55.5) v3(120,57.5)
GND_PRI_S: length 183.1
  TOP w0.2: 93.5,1.19 36.91,1.19 ; 49.67,1.1 36.77,1.1 36.81,1.14 36.86,1.2 47.6,1.2
  BOTTOM w0.2: 75.35,8.55 75.15,8.55
  BOTTOM w0.25: 27.85,10.82 U4.6 26.05,10.82 ; Q3.E 59.33,4.2 ; Q3.E 58.5,3.52 ; Q3.E 58.5,4.88 ; U4.5 27.88,11.47 ; U4.5 26.95,12.03 ; U4.5 26.02,11.47 ; 80.85,13.22 C16.2 ; C16.2 81.62,14 ; C16.2 80.08,14 ; D13.A 16.07,19.15 ; D13.A 17.93,19.15 ; D13.A 17,18.12 ; R1.2 33.58,6.75 ; R1.2 34.35,5.97 ; R1.2 35.12,6.75 ; R1.2 34.35,7.53 ; R5.2 35.12,2.75 ; R5.2 34.35,3.52 ; R5.2 33.58,2.75 ; R5.2 34.35,1.98 ; R15.2 73.58,5.75 ; R15.2 75.12,5.75 ; R15.2 74.35,4.97 ; C8.2 46.92,2 ; C8.2 45.38,2 ; C8.2 46.15,1.23 ; U1.4 37.88,7.97 ; C2.2 34.35,5.53 ; C2.2 33.58,4.75 ; C2.2 35.12,4.75 ; C2.2 34.35,3.98 ; U6.5 136.65,32.42 ; U6.5 137.57,33.09 ; U6.5 135.72,33.09 ; U4.4 22.12,11.47
  BOTTOM w0.3: C7.2 78,3.75 ; C7.2 79.7,3.75 ; C7.2 78.85,4.6 ; R57.2 145.25,33.45 ; R57.2 145.25,31.75 ; R57.2 144.4,32.6 ; R57.2 146.1,32.6 ; C43.2 31.25,10.45 ; C43.2 30.4,9.6 ; C43.2 32.1,9.6 ; C43.2 31.25,8.75 ; R61.2 20.4,14.65 ; R61.2 20.4,16.35 ; R61.2 21.25,15.5 ; R61.2 19.55,15.5 ; U6.4 144.35,33.09 ; U6.4 142.35,33.09 ; U6.4 143.35,32.34 ; C21.2 88.9,9.65 ; C21.2 88.9,11.35 ; C21.2 88.05,10.5 ; C21.2 89.75,10.5 ; C20.2 88.9,7.35 ; C20.2 88.9,5.65 ; C20.2 88.05,6.5 ; C20.2 89.75,6.5 ; C6.2 73.5,7.75 ; C6.2 74.35,8.6 ; C6.2 75.2,7.75 ; C19.2 88.9,3.65 ; C19.2 88.05,4.5 ; C19.2 89.75,4.5 ; C19.2 88.9,5.35 ; D3.A 71.2,9.5 ; D3.A 72.2,10.25 ; D3.A 73.2,9.5 ; D3.A 72.2,8.75 ; R41.2 88.9,9.35 ; R41.2 88.05,8.5 ; R41.2 89.75,8.5 ; R41.2 88.9,7.65 ; C14.2 75.4,11.25 ; C14.2 74.45,12.5 ; C14.2 76.35,12.5 ; C14.2 75.4,13.75 ; C17.2 41.65,2.1 ; C17.2 42.5,1.25 ; C17.2 43.35,2.1 ; C40.2 134.75,35.95 ; C40.2 135.6,35.1 ; C40.2 134.75,34.25 ; R20.2 73.5,9.75 ; R20.2 75.2,9.75 ; R20.2 74.35,8.9 ; R20.2 74.35,10.6 ; U3.1 79.95,5.84 ; U3.1 78.75,5.09 ; U3.1 77.55,5.84 ; ZD1.A 31.75,6.1 ; ZD1.A 29.75,6.1 ; ZD1.A 30.75,5 ; ZD1.A 30.75,7.2 ; C33.2 25,13.5 ; C33.2 24.15,14.35 ; C33.2 23.3,13.5 ; C35.2 147.25,31.75 ; C35.2 148.1,32.6 ; C35.2 146.4,32.6 ; C35.2 147.25,33.45 ; U7.3 33.5,12.9 ; U7.3 35,12.9 ; U7.3 34.25,11.9 ; C3.2 33.5,8.75 ; C3.2 35.2,8.75 ; C3.2 34.35,7.9 ; C3.2 34.35,9.6 ; Q4.E 63.95,5.85 ; Q4.E 64.7,6.75 ; Q4.E 63.95,7.65 ; R25.2 51.15,3.15
  BOTTOM w1: 90.5,17.5 TP1.1
  vias: v1(65.5,2.62) v2(20,6.5) v2(21.62,11.75) v2(21.98,6.47) v2(28.5,3) v2(30.75,8.25) v2(33,8.38) v2(33,2.75) v2(49,1.62) v2(51.02,1.62) v2(59.5,6) v2(65.3,9) v2(66.8,9) v2(68.05,9) v2(72.5,17.5) v2(73.3,13.6) v2(73.3,11.5) v2(73.4,4.3) v2(73.5,21) v2(75,21) v2(77,4.3) v2(78.8,14.5) v2(81.5,9.5) v2(81.5,7) v2(81.62,5) v2(84.5,13) v2(85,17.5) v2(85.5,4.5) v2(87.12,17.5) v2(89,17.5) v2(92,17.5) v2(136,31.62) v2(142.8,31.62)
GND_SEC: length 171.1
  TOP w0.4: v1(154.85,98.65) v1(154.85,106)
  BOTTOM w0.25: C62.1 171.58,38.17 ; C62.1 171.58,39.83 ; C62.1 169.92,39.83 ; C62.1 169.92,38.17 ; C56.1 183.58,76.17 ; C56.1 183.58,77.83 ; C56.1 181.92,76.17 ; C56.1 181.92,77.83 ; C59.1 169.92,68.33 ; C59.1 169.92,66.67 ; C59.1 171.58,68.33 ; C59.1 171.58,66.67 ; C60.1 169.92,58.83 ; C60.1 171.58,57.17 ; C60.1 169.92,57.17 ; C60.1 171.58,58.83 ; C57.1 171.58,76.17 ; C57.1 171.58,77.83 ; C57.1 169.92,76.17 ; C57.1 169.92,77.83 ; C61.1 171.58,47.67 ; C61.1 171.58,49.33 ; C61.1 169.92,49.33 ; C61.1 169.92,47.67 ; D26.A 147.82,61.8 ; D26.A 148.5,62.73 ; D26.A 148.5,60.88 ; D26.A 149.18,61.8 ; R114.2 151.75,61.08 ; R114.2 151.75,62.62 ; R114.2 150.97,61.85 ; R114.2 152.53,61.85 ; C67.1 155.42,52.17 ; C67.1 157.08,52.17 ; C67.1 155.42,53.83 ; C67.1 157.08,53.83 ; C66.1 155.42,61.67 ; C66.1 155.42,63.33 ; C66.1 157.08,63.33 ; C66.1 157.08,61.67 ; C55.2 176.78,123 ; C55.2 175.12,123 ; C55.2 175.95,121.97 ; C63.1 157.08,72.83 ; C63.1 155.42,71.17 ; C63.1 157.08,71.17 ; C63.1 155.42,72.83 ; C69.1 155.42,42.67 ; C69.1 157.08,44.33 ; C69.1 155.42,44.33 ; C69.1 157.08,42.67 ; R96.1 172.72,120.15 ; R96.1 173.5,120.92 ; R96.1 174.28,120.15
  BOTTOM w0.3: C81.2 170.9,30.6 ; C81.2 171.75,29.75 ; C81.2 170.9,28.9 ; C81.2 170.05,29.75 ; C58.2 181.35,120.15 ; C58.2 180.5,121 ; C58.2 179.65,120.15 ; C71.2 170.1,65.9 ; C71.2 169.05,64.75 ; C71.2 171.15,64.75 ; C71.2 170.1,63.6 ; C76.2 155.85,59.75 ; C76.2 156.9,60.9 ; C76.2 156.9,58.6 ; C65.2 156.5,14.45 ; C65.2 156.5,12.75 ; C65.2 155.65,13.6 ; C65.2 157.35,13.6 ; 157.8,17.89 U11.3 160.2,17.89 ; R104.2 155.65,19.15 ; R104.2 156.5,20 ; R104.2 156.5,18.3 ; R104.2 157.35,19.15 ; C77.2 157.95,50.25 ; C77.2 155.85,50.25 ; C77.2 156.9,51.4 ; C77.2 156.9,49.1 ; 174.35,104.15 R91.1 172.65,104.15 ; C74.2 170.1,46.9 ; C74.2 169.05,45.75 ; C74.2 170.1,44.6 ; C74.2 171.15,45.75 ; C72.2 170.35,56.4 ; C72.2 170.35,54.1 ; C72.2 171.4,55.25 ; C72.2 169.3,55.25 ; 171.25,27.12 C78.1 171.25,24.6 C80.2 ; C75.2 156.9,68.1 ; C75.2 156.9,70.4 ; C75.2 155.85,69.25 ; C75.2 157.95,69.25 ; R108.2 140.5,65.5 ; R108.2 140.5,63.8 ; R108.2 139.65,64.65 ; R108.2 141.35,64.65 ; C53.2 175.95,105.4 ; C53.2 175.95,107.6 ; C53.2 176.85,106.5 ; C53.2 175.05,106.5 ; C54.2 180.5,103.05 ; C54.2 181.35,103.9 ; C54.2 180.5,104.75 ; C54.2 179.65,103.9 ; U11.4 157.8,19.16 ; U11.4 159,19.9 ; U11.4 160.2,19.16 ; U10.3 143.5,67.65 ; U10.3 144.25,68.65 ; U10.3 142.75,68.65 ; U10.3 143.5,69.65 ; R109.1 157,37.65 ; R109.1 155.75,38.6 ; R109.1 157,39.55 ; R109.1 158.25,38.6 ; C50.1 155.7,108 ; C50.1 154.85,108.85 ; C50.1 154,108
  BOTTOM w0.4: v1(154.85,98.65) R89.2 ; v1(173.5,106) R91.1 173.5,104.1 ; C50.1 v1(154.85,106)
  BOTTOM w0.5: C47.2 147.9,82.1 ; C47.2 147.9,79.9 ; C47.2 150.1,79.9 ; C47.2 150.1,82.1 ; C79.2 168.04,5.96 ; C79.2 169.96,5.96 ; C79.2 168.04,4.04 ; C79.2 169.96,4.04
  BOTTOM w1: TB2.2 184.63,51.63 ; TB2.2 184.63,48.37 ; TB2.2 181.37,48.37 ; TB2.2 181.37,51.63 ; TB2.1 181.37,62.63 ; TB2.1 184.63,62.63 ; TB2.1 181.37,59.37 ; TB2.1 184.63,59.37
  vias: v2(138,64.88) v2(139.25,63.62) v2(140.88,66.12) v2(141.5,61.75) v2(144.75,59) v2(145,69.62) v2(146.5,63.25) v2(147.75,58) v2(148.62,60.5) v2(149.88,60.5) v2(150.5,57.12)
VCC-IC: length 159.8
  TOP w0.3: v1(83.4,18) 83.4,12.4 85.9,9.9 v1(85.9,7.12)
  TOP w0.4: v1(81.5,103) 71.75,93.25 71.75,89.5 70.25,88 64.5,88 63.5,87 63.5,70 65.5,68 65.5,20.5 66.33,19.68 v1(78.5,19.68)
  BOTTOM w0.3: v1(83.4,18) 83.4,19.25 82.97,19.68 81.33,19.68 D9.C 81.17,19.68 v1(78.5,19.68) ; U3.7 v1(85.9,7.12) 86.52,6.5 C20.1 C19.1
  BOTTOM w0.4: C41.2 88.88,112 85.62,108.75 80.75,108.75 79.75,107.75 79.75,104.6 80.25,104.1 C25.1 v1(81.5,103) 82.34,102.16 U5.3
  BOTTOM w0.8: C41.2 93.75,112 94.75,111 94.75,109.5 95.17,109.08 96.25,109.08
VCC_P1: length 340.8
  TOP w0.3: v1(52.25,5.75) 50.9,7.1 v1(50.9,12.9) ; v1(29.25,7.2) 39.17,7.2 41.38,5 v1(42.5,5)
  TOP w0.4: v1(81.25,15.12) 80.62,15.75 v1(64.62,15.75) 64.62,67.88 62.75,69.75 62.75,87.25 64.25,88.75 69.88,88.75 71,89.88 v1(71,93.75) 71,95 v1(79,103)
  BOTTOM w0.3: U4.8 25.98,9.53 25.38,10.12 25.38,12.12 25.12,12.38 22.75,12.38 22.35,12.78 C33.1 R60.1 ; U4.8 26.95,8.6 26.35,8 R75.1 R48.1 ; U4.8 28.05,9.53 28.12,9.6 R84.1 v1(29.25,7.2) ; v1(50.9,12.9) 50.9,14.1 51.8,15 55.3,15 56.05,15.75 v1(64.62,15.75) ; U1.8 42.7,5.7 42.5,5.5 v1(42.5,5) ; 134.75,36.91 C40.1 ; Q1.E v1(52.25,5.75) 52,6 R24.1 50.25,6 50.25,3.12 45.25,3.12 45.25,4.75 45,5 v1(42.5,5) ; v1(42.5,5) C17.1 41.6,3.9 41.5,4 R16.1
  BOTTOM w0.4: v1(71,93.75) R28.1 ; C22.2 93.75,121.75 92.75,120.75 92.75,115 92.12,114.38 90.25,114.38 85.38,109.5 80.5,109.5 79,108 v1(79,103) ; U6.8 136.65,36.9 C40.1 134.03,36.9 133.75,36.62 133.75,27.5 135,26.25 142.12,26.25 144.25,24.12 144.25,6 141.88,3.62 107.38,3.62 100.62,10.38 96.38,10.38 92.5,14.25 84.75,14.25 83.88,15.12 v1(81.25,15.12) 81.25,16.32
  BOTTOM w0.8: 96.67,126.5 96.67,122.92 C22.2
+HV: length 145.5
  BOTTOM w0.3: 136.12,48 137.12,49 R52.1
  BOTTOM w0.4: D15.C 70.25,45.25 70.5,45 R36.1 71.5,45
  BOTTOM w0.5: C24.1 81.92,60.67 ; C24.1 81.92,58.83 ; C24.1 80.08,60.67 ; C24.1 80.08,58.83
  BOTTOM w0.8: C31.2 131.55,41.05 ; C31.2 134.45,43.95 ; C31.2 134.45,41.05 ; C31.2 131.55,43.95 ; 80.69,62.56 76.12,67.12 76.12,71.62 73.5,74.25 73.5,79.5 ; C4.1 63.5,127.1 ; 63.5,127.1 C1.1 73.5,129 74.1,128.4 T1.1 ; 63.5,127.1 R10.1 60.23,127.1 59.38,126.25 59.38,121.88 56.88,119.38 56.88,93.5 59.5,90.88 59.5,85.38 65.38,79.5 73.5,79.5 ; C32.2 99.55,43.95 ; C32.2 102.45,43.95 ; C32.2 102.45,41.05 ; 73.5,79.5 R63.1
  BOTTOM w2: D15.C 87,48
  vias: v1(127,22.3) v1(127,20.7) v1(127,19.1) v1(127.5,23.1) v1(127.5,21.5) v1(127.5,19.9) v1(127.5,18.3) v1(128,22.3) v1(128,20.7) v1(128,19.1) v1(128.5,23.1) v1(128.5,21.5) v1(128.5,19.9) v1(128.5,18.3) v1(129,22.3) v1(129,20.7) v1(129,19.1) v1(129.5,23.1) v1(129.5,21.5) v1(129.5,19.9) v1(129.5,18.3) v1(130,22.3) v1(130,20.7) v1(130,19.1) v1(130.5,23.1) v1(130.5,21.5) v1(130.5,19.9) v1(130.5,18.3) v1(131,22.3) v1(131,20.7) v1(131,19.1) v1(131.5,23.1) v1(131.5,21.5) v1(131.5,19.9) v1(131.5,18.3) v1(132,22.3) v1(132,20.7) v1(132,19.1) v1(132.5,23.1) v1(132.5,21.5) v1(132.5,19.9) v1(132.5,18.3) v1(133,22.3) v1(133,20.7) v1(133,19.1) v1(133.5,23.1) v1(133.5,21.5) v1(133.5,19.9) v1(133.5,18.3) v1(134,22.3) v1(134,20.7) v1(134,19.1) v1(134.5,23.1) v1(134.5,21.5) v1(134.5,19.9) v1(134.5,18.3) v1(135,22.3) v1(135,20.7) v1(135,19.1) v1(135.5,23.1) v1(135.5,21.5) v1(135.5,19.9) v1(135.5,18.3) v1(136,22.3) v1(136,20.7) v1(136,19.1) v1(136.5,23.1) v1(136.5,21.5) v1(136.5,19.9) v1(136.5,18.3) v1(137,22.3) v1(137,20.7) v1(137,19.1) v1(137.5,23.1) v1(137.5,21.5) v1(137.5,19.9) v1(137.5,18.3) v1(138,22.3) v1(138,20.7) v1(138,19.1) v1(138.5,23.1) v1(138.5,21.5) v1(138.5,19.9) v1(138.5,18.3) v1(139,22.3) v1(139,20.7) v1(139,19.1) v1(139.5,23.1) v1(139.5,21.5) v1(139.5,19.9) v1(139.5,18.3) v1(140,22.3) v1(140,20.7) v1(140,19.1) v1(140.5,23.1) v1(140.5,21.5) v1(140.5,19.9) v1(140.5,18.3) v1(141,22.3) v1(141,20.7) v1(141,19.1)
ACINREC: length 18.6
  TOP w0.3: v1(13.25,17.88) 21,17.88 22,18.88 v1(22,22.8)
  BOTTOM w0.3: 13.25,19.32 v1(13.25,17.88) 14.38,17.88 14.75,17.5 R2.1 ; 22,24.07 v1(22,22.8)
ACINVDET1: length 13.3
  TOP w0.3: v1(52.12,11.88) 52.12,7.38 54.2,5.3 v1(56.4,5.3)
  BOTTOM w0.3: Q1.B 55.95,5.75 v1(56.4,5.3) ; D11.A 53,12.75 v1(52.12,11.88)
ACINVDET2: length 110.3
  TOP w0.4: v1(63.62,14.5) 63.62,67.88 62,69.5 62,87.5 64.25,89.75 v1(69.4,89.75)
  BOTTOM w0.3: v1(63.62,14.5) 61.5,14.5 61.25,14.25 61.25,10.88 58.52,8.15 R31.2 55.98,8.15 54.88,9.25 53.25,9.25 49.95,12.55 D12.A
  BOTTOM w0.4: v1(69.4,89.75) R30.2 69.4,92.5 69.15,92.75 67.85,92.75 67.6,93 R28.2
BLK: length 25.3
  BOTTOM w0.4: D19.A 70.7,104.08 72.12,105.5 74.88,105.5 75.5,104.88 75.5,102.9 78.7,99.7 83.33,99.7 83.61,99.99 U5.4 83.61,102.25 83.75,102.39 R58.1 83.85,103.75 85,103.75 85.1,103.85 C26.1
BW: length 33.8
  BOTTOM w0.4: R72.1 R71.1 97.9,104.15 98.25,104.5 98.25,112.42
  BOTTOM w0.8: 96.25,112.42 98.25,112.42 99.5,113.67 99.5,125 102.15,127.65 T2.1
FG1: length 5.4
  BOTTOM w0.5: C79.1 179.96,5.96 ; C79.1 179.96,4.04 ; C79.1 178.04,4.04 ; C79.1 178.04,5.96
  vias: v6(187,5)
FG2:
  vias: v5(5,130)
FG3: length 10
  BOTTOM w0.4: C13.2 4.88,43.12 ; C13.2 3.12,44.88 ; C13.2 3.12,43.12 ; C13.2 4.88,44.88 ; C15.2 4.88,31.62 ; C15.2 3.12,33.38 ; C15.2 3.12,31.62 ; C15.2 4.88,33.38
  vias: v5(5,5)
HI_GATE: length 10.8
  BOTTOM w0.4: R74.2 77,91.75 78.85,93.6 80.58,93.6 81.08,94.1 U5.15
HS: length 40.2
  TOP w0.4: Q7.S 85.04,71.56 82.5,74.1 v1(81,74.1) 81,79 77.75,82.25 v1(77.75,94)
  BOTTOM w0.4: v1(77.75,94) C38.1 78.75,95.1 79.15,95.5 U5.16 ; R81.2 v1(81,74.1)
  BOTTOM w0.8: T2.4 103.51,111.49 ; T2.4 105.99,111.49 ; T2.4 105.99,109.01 ; T2.4 103.51,109.01
HV+SENS: length 20.4
  BOTTOM w0.4: C35.1 R57.1 144.41,34.4 144.38,34.37 U6.3 142.12,34.37 140.95,33.2 D17.A
  BOTTOM w0.5: R56.2 143.88,41 145.25,39.62 R57.1
HVDET: length 57.4
  TOP w0.3: v2(52.75,3.95) 49.83,3.95 47.62,1.75 v2(36.15,1.75)
  BOTTOM w0.3: 30.5,1.25 30.75,1.5 ; 30.5,1.25 31,1.25 ; 30.5,1.25 15.4,1.25 15.15,1.5 R4.2 ; 30.75,1.5 31,1.25 ; 30.75,1.5 30.75,2.83 ; v2(52.75,3.95) D24.C 53.8,4.8 54.25,5.25 54.25,6.5 52.65,8.1 R9.1 ; 31,1.25 35.65,1.25 v2(36.15,1.75) R5.1 C2.1 R1.1 37.38,6.75 37.95,7.33 U1.3
ISENSE: length 31.8
  BOTTOM w0.3: 79.05,28.6 77.5,28.6 77,28.1 R19.1
  BOTTOM w0.4: C23.2 49.2,39.45 ; C23.2 49.2,37.55 ; C23.2 47.3,37.55 ; C23.2 47.3,39.45
  BOTTOM w0.8: R43.1 89.95,28.6 ; R43.1 88.5,29.75 ; R43.1 87.05,28.6 ; R44.1 84.5,29.75 ; R44.1 83.05,28.6 ; R44.1 85.95,28.6 ; 80.5,29.75 R45.1 ; R45.1 79.05,28.6 ; R45.1 82,28.6
ISNS_VCR: length 31.4
  TOP w0.8: C45.1 131.9,86.85 ; C45.1 134.1,84.65 ; C45.1 134.1,86.85 ; C45.1 131.9,84.65 ; T2.6 103.51,97.41 ; T2.6 105.99,99.89 ; T2.6 105.99,97.41 ; T2.6 103.51,99.89 ; C42.1 124.4,86.85 ; C42.1 126.6,86.85 ; C42.1 126.6,84.65 ; C42.1 124.4,84.65
  BOTTOM w0.4: C44.1 C46.1 101.25,92.5 102.5,93.75 102.5,96.4 T2.6
LO_GATE: length 12.6
  TOP w0.4: v1(89,93.12) v1(89,88.25)
  BOTTOM w0.4: U5.10 87.42,94.2 87.62,94 88.12,94 v1(89,93.12) ; R76.2 v1(89,88.25)
OR_GATE: length 23.2
  BOTTOM w0.3: U11.5 165.59,19.16 166.9,17.85 166.9,11.85 167.4,11.35 R116.2
  BOTTOM w0.4: R116.2 R115.2 R113.2
OTP: length 155.9
  TOP w0.3: v1(61.62,8) 60.75,7.12 55,7.12 53,9.12 53,12.25 48.95,16.3 43.2,16.3 42.3,15.4 42.3,11.5 41,10.2 21.32,10.2 21,9.88 v1(21,8)
  TOP w0.4: v1(61.62,8) 61.62,67.75 60.5,68.88 60.5,97.05 v1(59.55,98)
  BOTTOM w0.3: U4.1 23.05,8 ; 23.05,8 R75.2 ; 23.05,8 v1(21,8) 19.23,8 18.6,8.62 R69.2 ; Q4.B 62.05,7.25 61.75,7.55 61.75,7.88 v1(61.62,8)
  BOTTOM w0.4: Q5.B v1(59.55,98)
PC1_A: length 13.5
  BOTTOM w0.3: PC1.A 135.98,64.02 136.85,63.15 R102.1 138.25,63.15 139.2,62.2 139.2,58.67 140.12,57.75 141.62,57.75 142.28,58.4 R101.2
PC1_CA: length 19.2
  BOTTOM w0.3: PC1.CA 136.38,61.48 136.5,61.35 R102.2 138.15,61.35 138.6,60.9 138.6,58.4 139.88,57.12 141.88,57.12 142.25,57.5 144.62,57.5 145.72,58.6 R103.1 146.5,57.75 147.32,56.92 149,56.92
PFC_GATE: length 5.8
  BOTTOM w0.4: 86.25,12.57 86.33,12.65 R46.1 91.95,12.65 R42.1
RELAY_12V_ON_OFF: length 262.1
  TOP w0.4: v1(62.5,89.38) 61.25,88.12 61.25,69.12 62.62,67.75 v1(62.62,11.38) 64.2,9.8 v1(64.2,3)
  BOTTOM w0.3: 41.85,10.6 42.25,11 D4.A 49.62,11 50.12,10.5 50.12,9 52.6,9 53.35,8.25 Q1.C 54.95,8.25 55.95,7.25 58.5,7.25 v1(62.62,11.38) ; 41.85,10.6 R27.2 ; 41.85,10.6 41.45,11 37.75,11 36.5,12.25 36.5,13.25 35.75,14 33.38,14 32.5,13.12 27.62,13.12 21.15,19.6 R32.2 ; v1(64.2,3) 64.83,3.62 68.88,3.62 70.2,2.3 90.1,2.3 91.25,3.45 91.25,6.15 94.72,9.62
  BOTTOM w0.4: 94.72,9.62 100.38,9.62 107.12,2.88 142.25,2.88 145.12,5.75 145.12,24.38 141.4,28.1 R47.1 ; v1(62.5,89.38) 62.52,89.35 R50.1
RVCC: length 19.2
  BOTTOM w0.4: C37.1 C36.1 88.83,91.55 90.03,90.35 R79.1 90.75,86.58 90.83,86.5 ; C37.1 C39.1 81.15,91.55 81,91.4 R83.2 ; C37.1 84.75,93.12 84.89,93.26 U5.12
SIG219: length 5
  BOTTOM w0.4: C9.1 50.12,95.88 ; C9.1 50.12,94.12 ; C9.1 51.88,94.12 ; C9.1 51.88,95.88
SIG222: length 53.5
  BOTTOM w0.4: C15.1 14,29.38 13.25,28.62 R12.1 ; C12.1 54.12,71.37 ; C12.1 55.88,71.37 ; C12.1 54.12,73.13 ; C12.1 55.88,73.13
  BOTTOM w0.5: D10.3 41.37,49.62 ; D10.3 41.37,51.88 ; D10.3 43.63,51.88 ; D10.3 43.63,49.62
  BOTTOM w0.8: C15.1 27.9,32.5 42.5,47.1 42.5,48.7
SIG226: length 38.7
  TOP w0.4: v1(14.38,41.38) 19,36.75 19,32 v1(22,29)
  BOTTOM w0.2: 45.75,78.4 40.23,78.4
  BOTTOM w0.25: C13.1 13.17,43.17 ; C13.1 13.17,44.83 ; C13.1 14.83,44.83 ; C13.1 14.83,43.17
  BOTTOM w0.3: v1(22,29) 22,27.43
  BOTTOM w0.4: C12.2 55.88,88.13 ; C12.2 55.88,86.37 ; C12.2 54.12,86.37 ; C12.2 54.12,88.13
  BOTTOM w0.5: D10.2 36.13,49.62 ; D10.2 36.13,51.88 ; D10.2 33.87,51.88 ; D10.2 33.87,49.62
SIG231:
  vias: v1(107,27.18) v1(107,25.57) v1(107,23.98) v1(107,22.38) v1(107,20.77) v1(107,19.18) v1(107,17.57) v1(107,15.97) v1(107.5,26.38) v1(107.5,24.77) v1(107.5,23.18) v1(107.5,21.57) v1(107.5,19.98) v1(107.5,18.38) v1(107.5,16.77) v1(108,27.18) v1(108,25.57) v1(108,23.98) v1(108,22.38) v1(108,20.77) v1(108,19.18) v1(108,17.57) v1(108,15.97) v1(108.5,26.38) v1(108.5,24.77) v1(108.5,23.18) v1(108.5,21.57) v1(108.5,19.98) v1(108.5,18.38) v1(108.5,16.77) v1(109,27.18) v1(109,25.57) v1(109,23.98) v1(109,22.38) v1(109,20.77) v1(109,19.18) v1(109,17.57) v1(109,15.97) v1(109.5,26.38) v1(109.5,24.77) v1(109.5,23.18) v1(109.5,21.57) v1(109.5,19.98) v1(109.5,18.38) v1(109.5,16.77) v1(110,27.18) v1(110,25.57) v1(110,23.98) v1(110,22.38) v1(110,20.77) v1(110,19.18) v1(110,17.57) v1(110,15.97) v1(110.5,26.38) v1(110.5,24.77) v1(110.5,23.18) v1(110.5,21.57) v1(110.5,19.98) v1(110.5,18.38) v1(110.5,16.77) v1(111,27.18) v1(111,25.57) v1(111,23.98) v1(111,22.38) v1(111,20.77) v1(111,19.18) v1(111,17.57) v1(111,15.97) v1(111.5,26.38) v1(111.5,24.77) v1(111.5,23.18) v1(111.5,21.57) v1(111.5,19.98) v1(111.5,18.38) v1(111.5,16.77) v1(112,27.18) v1(112,25.57) v1(112,23.98) v1(112,22.38) v1(112,20.77) v1(112,19.18) v1(112,17.57) v1(112,15.97) v1(112.5,26.38) v1(112.5,24.77) v1(112.5,23.18) v1(112.5,21.57) v1(112.5,19.98) v1(112.5,18.38) v1(112.5,16.77) v1(113,27.18) v1(113,25.57) v1(113,23.98) v1(113,22.38) v1(113,20.77) v1(113,19.18) v1(113,17.57) v1(113,15.97) v1(113.5,26.38) v1(113.5,24.77) v1(113.5,23.18) v1(113.5,21.57) v1(113.5,19.98) v1(113.5,18.38) v1(113.5,16.77) v1(114,27.18) v1(114,25.57) v1(114,23.98) v1(114,22.38) v1(114,20.77) v1(114,19.18) v1(114,17.57) v1(114,15.97) v1(114.5,26.38) v1(114.5,24.77) v1(114.5,23.18) v1(114.5,21.57) v1(114.5,19.98) v1(114.5,18.38) v1(114.5,16.77) v1(115,27.18) v1(115,25.57) v1(115,23.98) v1(115,22.38) v1(115,20.77) v1(115,19.18) v1(115,17.57) v1(115,15.97) v1(115.5,26.38) v1(115.5,24.77) v1(115.5,23.18) v1(115.5,21.57) v1(115.5,19.98) v1(115.5,18.38) v1(115.5,16.77) v1(116,27.18) v1(116,25.57) v1(116,23.98) v1(116,22.38) v1(116,20.77) v1(116,19.18) v1(116,17.57) v1(116,15.97) v1(116.5,26.38) v1(116.5,24.77) v1(116.5,23.18) v1(116.5,21.57) v1(116.5,19.98) v1(116.5,18.38) v1(116.5,16.77) v1(117,27.18) v1(117,25.57) v1(117,23.98) v1(117,22.38) v1(117,20.77) v1(117,19.18) v1(117,17.57) v1(117,15.97) v1(117.5,26.38) v1(117.5,24.77) v1(117.5,23.18) v1(117.5,21.57) v1(117.5,19.98) v1(117.5,18.38) v1(117.5,16.77) v1(118,27.18) v1(118,25.57) v1(118,23.98) v1(118,22.38) v1(118,20.77) v1(118,19.18) v1(118,17.57) v1(118,15.97) v1(118.5,26.38) v1(118.5,24.77) v1(118.5,23.18) v1(118.5,21.57) v1(118.5,19.98) v1(118.5,18.38) v1(118.5,16.77) v1(119,27.18) v1(119,25.57) v1(119,23.98) v1(119,22.38) v1(119,20.77) v1(119,19.18) v1(119,17.57) v1(119,15.97) v1(119.5,26.38) v1(119.5,24.77) v1(119.5,23.18) v1(119.5,21.57) v1(119.5,19.98) v1(119.5,18.38) v1(119.5,16.77) v1(120,27.18) v1(120,25.57) v1(120,23.98) v1(120,22.38) v1(120,20.77) v1(120,19.18) v1(120,17.57) v1(120,15.97) v1(120.5,26.38) v1(120.5,24.77) v1(120.5,23.18) v1(120.5,21.57) v1(120.5,19.98) v1(120.5,18.38) v1(120.5,16.77) v1(121,27.18) v1(121,25.57) v1(121,23.98) v1(121,22.38) v1(121,20.77) v1(121,19.18) v1(121,17.57) v1(121,15.97) v1(131,12.5) v1(131.5,11.5) v1(132,12.5) v1(132.5,11.5) v1(133,12.5) v1(133.5,11.5) v1(134,12.5) v1(134.5,11.5) v1(135,12.5) v1(135.5,11.5) v1(136,12.5) v1(136.5,11.5) v1(137,12.5) v1(137.5,11.5) v1(138,12.5)
